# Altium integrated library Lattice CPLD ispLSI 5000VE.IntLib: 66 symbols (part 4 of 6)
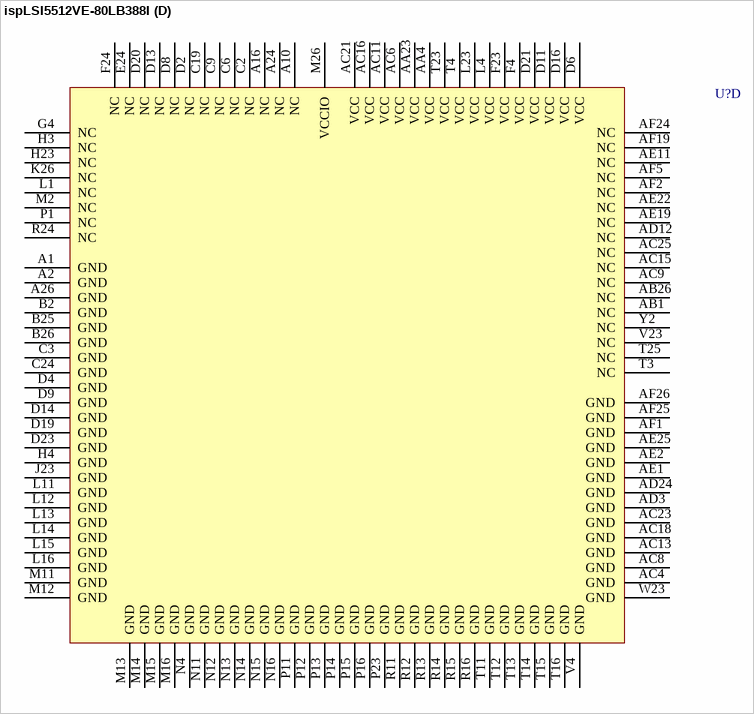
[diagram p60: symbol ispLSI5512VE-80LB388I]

## ispLSI5512VE-80LB388I
designator U?
ispLSI 5512VE SuperWIDE High Density PLD with 256 User I/Os, 12 ns, 3.3 V, Industrial Grade
footprint BGA388 (BGA, 388-Leads, Body 35x35mm, Pitch 1.27mm)
3D model 5512VE-BGA388 (388-Ball Ball Grid Array (BGA388))
part A pins: AA1 I/O18 (io), AA2 I/O16 (io), AA3 I/O22 (io), AA24 I/O114 (io), AA25 I/O112 (io), AA26 I/O115 (io), AB2 I/O20 (io), AB3 I/O26 (io), AB4 I/O24 (io), AB23 I/O109 (io), AB24 I/O110 (io), AB25 I/O108 (io), AC1 I/O25 (io), AC2 I/O23 (io), AC3 I/O28 (io), AC5 I/O37 (io), AC7 I/O41 (io), AC10 I/O56 (io), AC12 I/O64 (io), AC14 I/O68 (io), AC17 I/O79 (io), AC19 I/O86 (io), AC20 I/O90 (io), AC22 I/O97 (io), AC24 I/O106 (io), AC26 I/O107 (io), AD1 I/O29 (io), AD2 I/O27 (io), AD4 I/O34 (io), AD5 I/O38 (io), AD6 I/O42 (io), AD7 I/O46 (io), AD8 I/O50 (io), AD9 I/O54 (io), AD10 I/O58 (io), AD11 I/O62 (io), AD14 I/O70 (io), AD15 I/O73 (io), AD16 I/O77 (io), AD17 I/O81 (io), AD18 I/O84 (io), AD19 I/O88 (io), AD20 I/O92 (io), AD21 I/O95 (io), AD22 I/O99 (io), AD23 I/O101 (io), AD25 I/O104 (io), AD26 I/O105 (io), AE3 I/O31 (io), AE4 I/O33 (io), AE5 I/O36 (io), AE6 I/O40 (io), AE7 I/O44 (io), AE8 I/O47 (io), AE9 I/O51 (io), AE10 I/O53 (io), AE12 I/O60 (io), AE13 I/O63 (io), AE14 I/O67 (io), AE15 I/O69 (io), AE16 I/O72 (io), AE17 I/O76 (io), AE18 I/O80 (io), AE20 I/O85 (io), AE21 I/O89 (io), AE23 I/O96 (io), AE24 I/O100 (io), AE26 I/O103 (io), AF3 I/O32 (io), AF4 I/O35 (io), AF6 I/O43 (io), AF7 I/O45 (io), AF8 I/O49 (io), AF9 I/O52 (io), AF10 I/O55 (io), AF11 I/O59 (io), AF12 I/O61 (io), AF13 I/O65 (io), AF15 I/O71 (io), AF16 I/O74 (io), AF17 I/O78 (io), AF18 I/O82 (io), AF20 I/O87 (io), AF21 I/O91 (io), AF22 I/O94 (io), AF23 I/O98 (io), M25 I/O143 (io), N23 I/O140 (io), N25 I/O139 (io), N26 I/O141 (io), P24 I/O142 (io), P25 I/O135 (io), P26 I/O137 (io), R4 I/O1 (io), R23 I/O136 (io), R25 I/O132 (io), R26 I/O133 (io), T1 I/O0/TOE (io), T24 I/O134 (io), T26 I/O131 (io), U1 I/O4 (io), U2 I/O2 (io), U3 I/O7 (io), U4 I/O5 (io), U23 I/O128 (io), U24 I/O130 (io), U25 I/O125 (io), U26 I/O127 (io), V1 I/O8 (io), V2 I/O6 (io), V3 I/O11 (io), V24 I/O126 (io), V25 I/O123 (io), V26 I/O124 (io), W1 I/O10 (io), W2 I/O9 (io), W3 I/O15 (io), W4 I/O13 (io), W24 I/O122 (io), W25 I/O119 (io), W26 I/O121 (io), Y1 I/O14 (io), Y3 I/O19 (io), Y4 I/O17 (io), Y23 I/O113 (io), Y24 I/O118 (io), Y25 I/O116 (io), Y26 I/O117 (io)
part B pins: A3 I/O246 (io), A4 I/O242 (io), A5 I/O238 (io), A6 I/O235 (io), A7 I/O231 (io), A8 I/O228 (io), A9 I/O226 (io), A11 I/O218 (io), A12 I/O215 (io), A14 I/O209 (io), A15 I/O205 (io), A17 I/O199 (io), A18 I/O196 (io), A19 I/O193 (io), A20 I/O189 (io), A21 I/O187 (io), A22 I/O183 (io), A23 I/O179/CLK2 (io), A25 I/O174 (io), B1 I/O247 (io), B3 I/O244 (io), B4 I/O240 (io), B5 I/O237 (io), B6 I/O233 (io), B7 I/O229 (io), B8 I/O227 (io), B9 I/O224 (io), B10 I/O220 (io), B11 I/O216 (io), B12 I/O213 (io), B13 I/O211 (io), B14 I/O207 (io), B15 I/O204 (io), B16 I/O201 (io), B17 I/O197/CLK3 (io), B18 I/O195 (io), B19 I/O191 (io), B20 I/O188 (io), B21 I/O184 (io), B22 I/O180 (io), B23 I/O177 (io), B24 I/O175 (io), C1 I/O249 (io), C4 I/O245 (io), C5 I/O243 (io), C7 I/O236 (io), C8 I/O232 (io), C10 I/O225 (io), C11 I/O221 (io), C12 I/O217 (io), C13 I/O214 (io), C15 I/O210 (io), C16 I/O206 (io), C17 I/O202 (io), C18 I/O198 (io), C20 I/O190 (io), C21 I/O186 (io), C22 I/O182 (io), C23 I/O178 (io), C25 I/O171 (io), C26 I/O173 (io), D1 I/O251 (io), D3 I/O250 (io), D5 I/O241 (io), D7 I/O234 (io), D10 I/O223 (io), D12 I/O219 (io), D15 I/O208 (io), D17 I/O200 (io), D18 I/O192 (io), D22 I/O181 (io), D24 I/O172 (io), D25 I/O168 (io), D26 I/O170 (io), E1 I/O255 (io), E2 I/O252 (io), E3 I/O254 (io), E4 I/O253 (io), E23 I/O169 (io), E25 I/O165 (io), E26 I/O166 (io), F1 I/O259 (io), F2 I/O256 (io), F3 I/O258 (io), F25 I/O161 (io), F26 I/O163 (io), G1 I/O261 (io), G2 I/O260 (io), G3 I/O262 (io), G23 I/O162 (io), G24 I/O164 (io), G25 I/O157 (io), G26 I/O159 (io), H1 I/O265 (io), H2 I/O263 (io), H24 I/O160 (io), H25 I/O154 (io), H26 I/O155 (io), J1 I/O268 (io), J2 I/O267 (io), J3 I/O270 (io), J4 I/O264 (io), J24 I/O156 (io), J25 I/O151 (io), J26 I/O153 (io), K1 I/O271 (io), K2 I/O269 (io), K3 I/O274 (io), K4 I/O272 (io), K23 I/O150 (io), K24 I/O152 (io), K25 I/O147 (io), L2 I/O273 (io), L3 I/O277 (io), L24 I/O148 (io), L26 I/O145 (io), M1 I/O276 (io), M3 I/O281 (io), M4 I/O279 (io), M23 I/O146 (io), M24 I/O144 (io), N1 I/O280 (io), N2 I/O278 (io), N3 I/O285 (io), P2 I/O282 (io), P3 I/O287 (io), P4 I/O283 (io), R2 I/O286 (io)
part C pins: A13 CLK0 (in), AD13 GOE1 (in), AF14 GOE0 (in), C14 CLK1 (in), L25 RESET (in), N24 TDO (out), R1 TMS (in), R3 TDI (in), T2 TCK (in)
part D pins: A1 GND (power), A2 GND (power), A10 NC, A16 NC, A24 NC, A26 GND (power), AA4 VCC (power), AA23 VCC (power), AB1 NC, AB26 NC, AC4 GND (power), AC6 VCC (power), AC8 GND (power), AC9 NC, AC11 VCC (power), AC13 GND (power), AC15 NC, AC16 VCC (power), AC18 GND (power), AC21 VCC (power), AC23 GND (power), AC25 NC, AD3 GND (power), AD12 NC, AD24 GND (power), AE1 GND (power), AE2 GND (power), AE11 NC, AE19 NC, AE22 NC, AE25 GND (power), AF1 GND (power), AF2 NC, AF5 NC, AF19 NC, AF24 NC, AF25 GND (power), AF26 GND (power), B2 GND (power), B25 GND (power), B26 GND (power), C2 NC, C3 GND (power), C6 NC, C9 NC, C19 NC, C24 GND (power), D2 NC, D4 GND (power), D6 VCC (power), D8 NC, D9 GND (power), D11 VCC (power), D13 NC, D14 GND (power), D16 VCC (power), D19 GND (power), D20 NC, D21 VCC (power), D23 GND (power), E24 NC, F4 VCC (power), F23 VCC (power), F24 NC, G4 NC, H3 NC, H4 GND (power), H23 NC, J23 GND (power), K26 NC, L1 NC, L4 VCC (power), L11 GND (power), L12 GND (power), L13 GND (power), L14 GND (power), L15 GND (power), L16 GND (power), L23 VCC (power), M2 NC, M11 GND (power), M12 GND (power), M13 GND (power), M14 GND (power), M15 GND (power), M16 GND (power), M26 VCCIO (power), N4 GND (power), N11 GND (power), N12 GND (power), N13 GND (power), N14 GND (power), N15 GND (power), N16 GND (power), P1 NC, P11 GND (power), P12 GND (power), P13 GND (power), P14 GND (power), P15 GND (power), P16 GND (power), P23 GND (power), R11 GND (power), R12 GND (power), R13 GND (power), R14 GND (power), R15 GND (power), R16 GND (power), R24 NC, T3 NC, T4 VCC (power), T11 GND (power), T12 GND (power), T13 GND (power), T14 GND (power), T15 GND (power), T16 GND (power), T23 VCC (power), T25 NC, V4 GND (power), V23 NC, W23 GND (power), Y2 NC

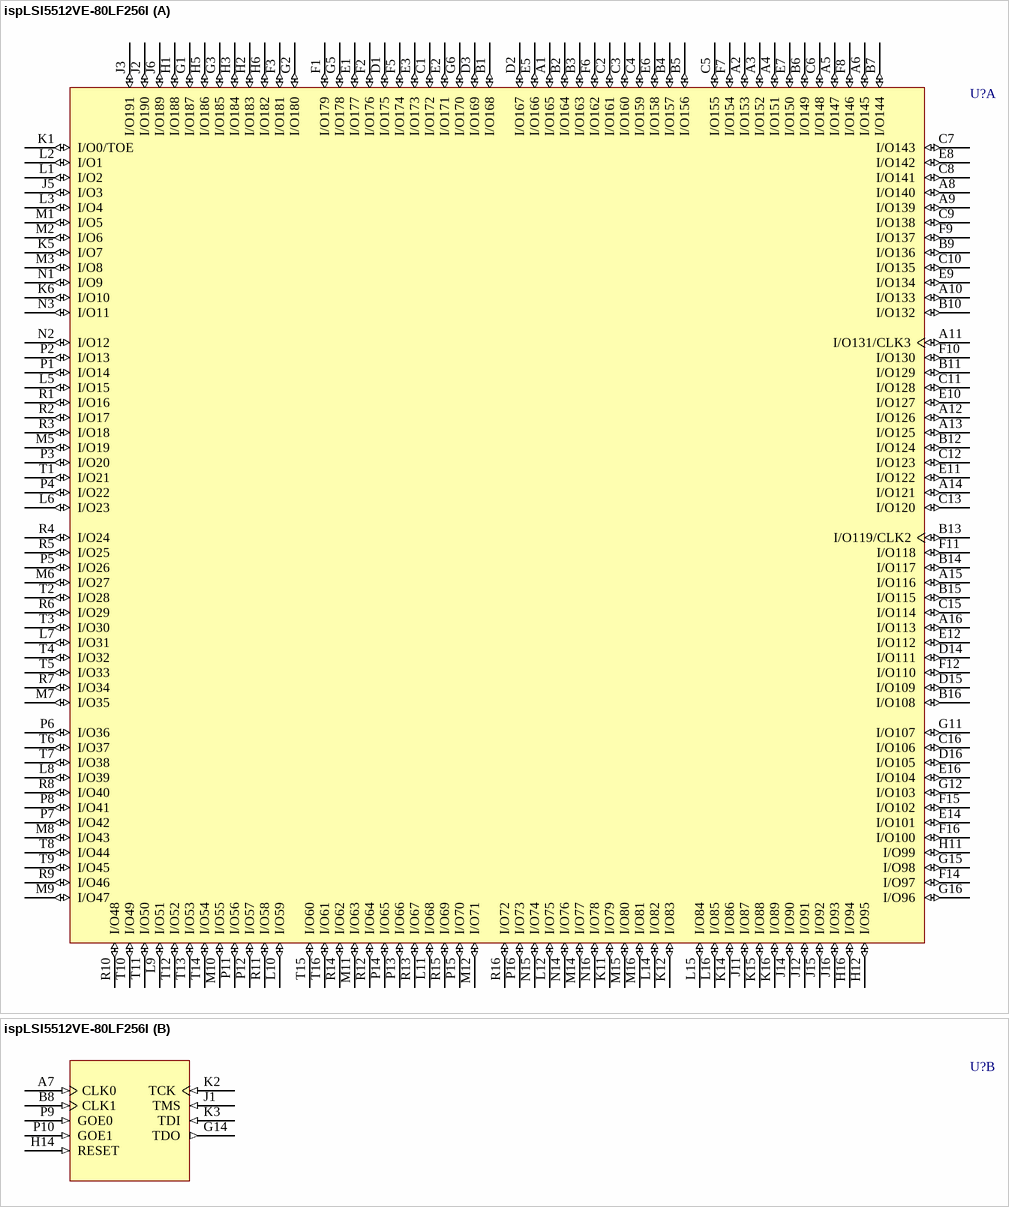
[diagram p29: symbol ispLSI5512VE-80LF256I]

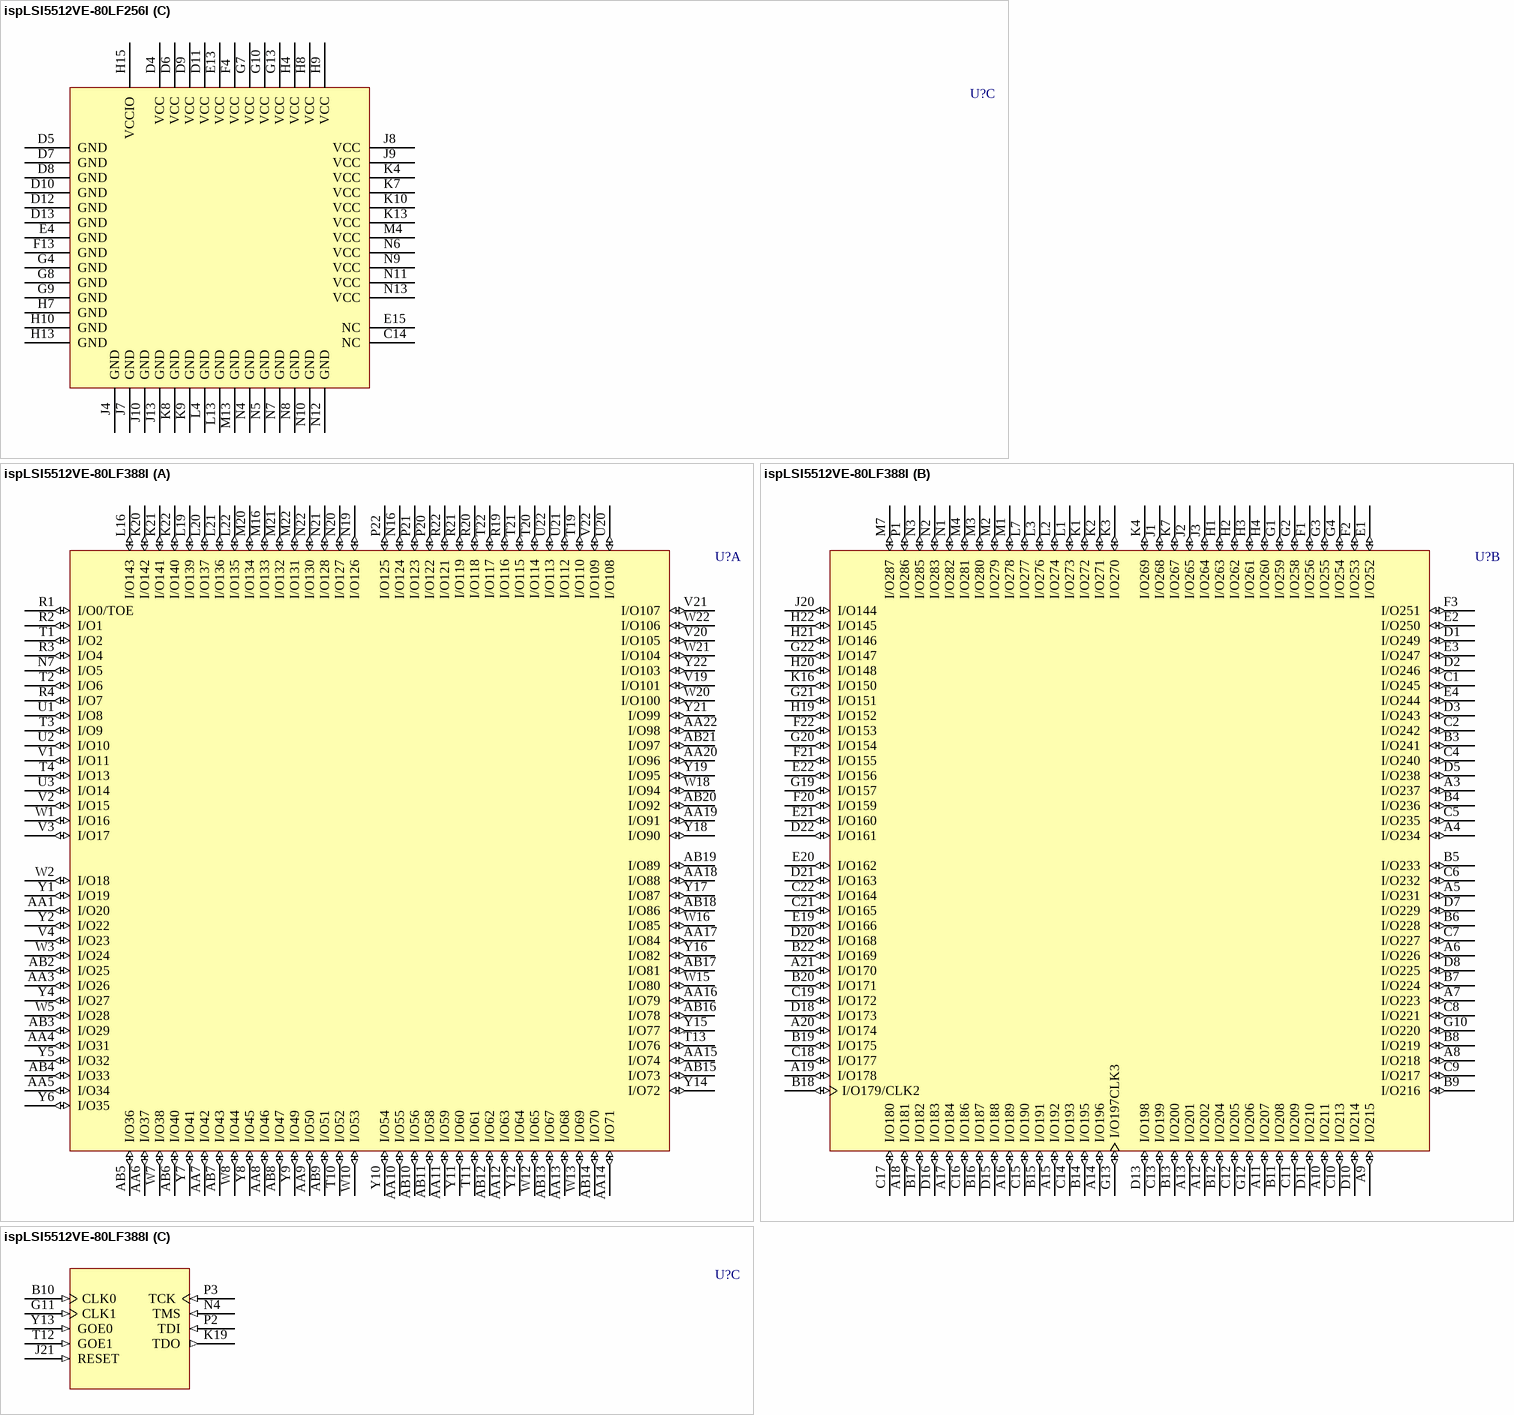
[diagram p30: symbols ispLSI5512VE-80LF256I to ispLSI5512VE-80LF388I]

## ispLSI5512VE-80LF256I
designator U?
ispLSI 5512VE SuperWIDE High Density PLD with 192 User I/Os, 12 ns, 3.3 V, Industrial Grade
footprint fpBGA256 (BGA, 256-Leads, Body 17x17mm, Pitch 1mm)
3D model 5512VE-fpBGA256 (256-Ball Fine Pitch Ball Grid Array (fpBGA256))
part A pins: A1 I/O165 (io), A2 I/O153 (io), A3 I/O152 (io), A4 I/O151 (io), A5 I/O147 (io), A6 I/O145 (io), A8 I/O140 (io), A9 I/O139 (io), A10 I/O133 (io), A11 I/O131/CLK3 (io), A12 I/O126 (io), A13 I/O125 (io), A14 I/O121 (io), A15 I/O116 (io), A16 I/O113 (io), B1 I/O168 (io), B2 I/O164 (io), B3 I/O163 (io), B4 I/O157 (io), B5 I/O156 (io), B6 I/O149 (io), B7 I/O144 (io), B9 I/O136 (io), B10 I/O132 (io), B11 I/O129 (io), B12 I/O124 (io), B13 I/O119/CLK2 (io), B14 I/O117 (io), B15 I/O115 (io), B16 I/O108 (io), C1 I/O172 (io), C2 I/O161 (io), C3 I/O160 (io), C4 I/O159 (io), C5 I/O155 (io), C6 I/O148 (io), C7 I/O143 (io), C8 I/O141 (io), C9 I/O138 (io), C10 I/O135 (io), C11 I/O128 (io), C12 I/O123 (io), C13 I/O120 (io), C15 I/O114 (io), C16 I/O106 (io), D1 I/O175 (io), D2 I/O167 (io), D3 I/O169 (io), D14 I/O111 (io), D15 I/O109 (io), D16 I/O105 (io), E1 I/O177 (io), E2 I/O171 (io), E3 I/O173 (io), E5 I/O166 (io), E6 I/O158 (io), E7 I/O150 (io), E8 I/O142 (io), E9 I/O134 (io), E10 I/O127 (io), E11 I/O122 (io), E12 I/O112 (io), E14 I/O101 (io), E16 I/O104 (io), F1 I/O179 (io), F2 I/O176 (io), F3 I/O181 (io), F5 I/O174 (io), F6 I/O162 (io), F7 I/O154 (io), F8 I/O146 (io), F9 I/O137 (io), F10 I/O130 (io), F11 I/O118 (io), F12 I/O110 (io), F14 I/O97 (io), F15 I/O102 (io), F16 I/O100 (io), G1 I/O187 (io), G2 I/O180 (io), G3 I/O185 (io), G5 I/O178 (io), G6 I/O170 (io), G11 I/O107 (io), G12 I/O103 (io), G15 I/O98 (io), G16 I/O96 (io), H1 I/O188 (io), H2 I/O183 (io), H3 I/O184 (io), H5 I/O186 (io), H6 I/O182 (io), H11 I/O99 (io), H12 I/O95 (io), H16 I/O94 (io), J2 I/O190 (io), J3 I/O191 (io), J5 I/O3 (io), J6 I/O189 (io), J11 I/O87 (io), J12 I/O91 (io), J14 I/O90 (io), J15 I/O92 (io), J16 I/O93 (io), K1 I/O0/TOE (io), K5 I/O7 (io), K6 I/O10 (io), K11 I/O79 (io), K12 I/O83 (io), K14 I/O86 (io), K15 I/O88 (io), K16 I/O89 (io), L1 I/O2 (io), L2 I/O1 (io), L3 I/O4 (io), L5 I/O15 (io), L6 I/O23 (io), L7 I/O31 (io), L8 I/O39 (io), L9 I/O51 (io), L10 I/O59 (io), L11 I/O68 (io), L12 I/O75 (io), L14 I/O82 (io), L15 I/O84 (io), L16 I/O85 (io), M1 I/O5 (io), M2 I/O6 (io), M3 I/O8 (io), M5 I/O19 (io), M6 I/O27 (io), M7 I/O35 (io), M8 I/O43 (io), M9 I/O47 (io), M10 I/O55 (io), M11 I/O63 (io), M12 I/O71 (io), M14 I/O77 (io), M15 I/O80 (io), M16 I/O81 (io), N1 I/O9 (io), N2 I/O12 (io), N3 I/O11 (io), N14 I/O76 (io), N15 I/O74 (io), N16 I/O78 (io), P1 I/O14 (io), P2 I/O13 (io), P3 I/O20 (io), P4 I/O22 (io), P5 I/O26 (io), P6 I/O36 (io), P7 I/O42 (io), P8 I/O41 (io), P11 I/O56 (io), P12 I/O57 (io), P13 I/O66 (io), P14 I/O65 (io), P15 I/O70 (io), P16 I/O73 (io), R1 I/O16 (io), R2 I/O17 (io), R3 I/O18 (io), R4 I/O24 (io), R5 I/O25 (io), R6 I/O29 (io), R7 I/O34 (io), R8 I/O40 (io), R9 I/O46 (io), R10 I/O48 (io), R11 I/O58 (io), R12 I/O64 (io), R13 I/O67 (io), R14 I/O62 (io), R15 I/O69 (io), R16 I/O72 (io), T1 I/O21 (io), T2 I/O28 (io), T3 I/O30 (io), T4 I/O32 (io), T5 I/O33 (io), T6 I/O37 (io), T7 I/O38 (io), T8 I/O44 (io), T9 I/O45 (io), T10 I/O49 (io), T11 I/O50 (io), T12 I/O52 (io), T13 I/O53 (io), T14 I/O54 (io), T15 I/O60 (io), T16 I/O61 (io)
part B pins: A7 CLK0 (in), B8 CLK1 (in), G14 TDO (out), H14 RESET (in), J1 TMS (in), K2 TCK (in), K3 TDI (in), P9 GOE0 (in), P10 GOE1 (in)
part C pins: C14 NC, D4 VCC (power), D5 GND (power), D6 VCC (power), D7 GND (power), D8 GND (power), D9 VCC (power), D10 GND (power), D11 VCC (power), D12 GND (power), D13 GND (power), E4 GND (power), E13 VCC (power), E15 NC, F4 VCC (power), F13 GND (power), G4 GND (power), G7 VCC (power), G8 GND (power), G9 GND (power), G10 VCC (power), G13 VCC (power), H4 VCC (power), H7 GND (power), H8 VCC (power), H9 VCC (power), H10 GND (power), H13 GND (power), H15 VCCIO (power), J4 GND (power), J7 GND (power), J8 VCC (power), J9 VCC (power), J10 GND (power), J13 GND (power), K4 VCC (power), K7 VCC (power), K8 GND (power), K9 GND (power), K10 VCC (power), K13 VCC (power), L4 GND (power), L13 GND (power), M4 VCC (power), M13 GND (power), N4 GND (power), N5 GND (power), N6 VCC (power), N7 GND (power), N8 GND (power), N9 VCC (power), N10 GND (power), N11 VCC (power), N12 GND (power), N13 VCC (power)

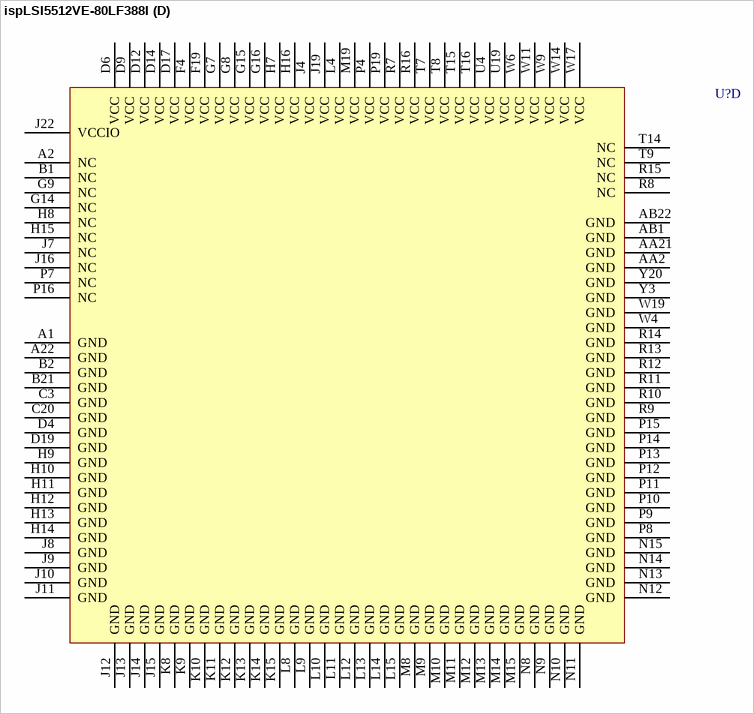
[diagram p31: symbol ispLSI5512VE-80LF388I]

## ispLSI5512VE-80LF388I
designator U?
ispLSI 5512VE SuperWIDE High Density PLD with 256 User I/Os, 12 ns, 3.3 V, Industrial Grade
footprint fpBGA388 (BGA, 388-Leads, Body 23x23mm, Pitch 1mm)
3D model 5512VE-fpBGA388 (388-Ball Fine Pitch Ball Grid Array (fpBGA388))
part A pins: AA1 I/O20 (io), AA3 I/O26 (io), AA4 I/O31 (io), AA5 I/O34 (io), AA6 I/O37 (io), AA7 I/O42 (io), AA8 I/O46 (io), AA9 I/O50 (io), AA10 I/O55 (io), AA11 I/O59 (io), AA12 I/O63 (io), AA13 I/O68 (io), AA14 I/O71 (io), AA15 I/O74 (io), AA16 I/O79 (io), AA17 I/O84 (io), AA18 I/O88 (io), AA19 I/O91 (io), AA20 I/O96 (io), AA22 I/O98 (io), AB2 I/O25 (io), AB3 I/O29 (io), AB4 I/O33 (io), AB5 I/O36 (io), AB6 I/O40 (io), AB7 I/O43 (io), AB8 I/O47 (io), AB9 I/O51 (io), AB10 I/O56 (io), AB11 I/O58 (io), AB12 I/O62 (io), AB13 I/O67 (io), AB14 I/O70 (io), AB15 I/O73 (io), AB16 I/O78 (io), AB17 I/O81 (io), AB18 I/O86 (io), AB19 I/O89 (io), AB20 I/O92 (io), AB21 I/O97 (io), K20 I/O142 (io), K21 I/O141 (io), K22 I/O140 (io), L16 I/O143 (io), L19 I/O139 (io), L20 I/O137 (io), L21 I/O136 (io), L22 I/O135 (io), M16 I/O133 (io), M20 I/O134 (io), M21 I/O132 (io), M22 I/O131 (io), N7 I/O5 (io), N16 I/O124 (io), N19 I/O126 (io), N20 I/O127 (io), N21 I/O128 (io), N22 I/O130 (io), P20 I/O122 (io), P21 I/O123 (io), P22 I/O125 (io), R1 I/O0/TOE (io), R2 I/O1 (io), R3 I/O4 (io), R4 I/O7 (io), R19 I/O116 (io), R20 I/O118 (io), R21 I/O119 (io), R22 I/O121 (io), T1 I/O2 (io), T2 I/O6 (io), T3 I/O9 (io), T4 I/O13 (io), T10 I/O52 (io), T11 I/O61 (io), T13 I/O76 (io), T19 I/O110 (io), T20 I/O114 (io), T21 I/O115 (io), T22 I/O117 (io), U1 I/O8 (io), U2 I/O10 (io), U3 I/O14 (io), U20 I/O108 (io), U21 I/O112 (io), U22 I/O113 (io), V1 I/O11 (io), V2 I/O15 (io), V3 I/O17 (io), V4 I/O23 (io), V19 I/O101 (io), V20 I/O105 (io), V21 I/O107 (io), V22 I/O109 (io), W1 I/O16 (io), W2 I/O18 (io), W3 I/O24 (io), W5 I/O28 (io), W7 I/O38 (io), W8 I/O44 (io), W10 I/O53 (io), W12 I/O65 (io), W13 I/O69 (io), W15 I/O80 (io), W16 I/O85 (io), W18 I/O94 (io), W20 I/O100 (io), W21 I/O104 (io), W22 I/O106 (io), Y1 I/O19 (io), Y2 I/O22 (io), Y4 I/O27 (io), Y5 I/O32 (io), Y6 I/O35 (io), Y7 I/O41 (io), Y8 I/O45 (io), Y9 I/O49 (io), Y10 I/O54 (io), Y11 I/O60 (io), Y12 I/O64 (io), Y14 I/O72 (io), Y15 I/O77 (io), Y16 I/O82 (io), Y17 I/O87 (io), Y18 I/O90 (io), Y19 I/O95 (io), Y21 I/O99 (io), Y22 I/O103 (io)
part B pins: A3 I/O237 (io), A4 I/O234 (io), A5 I/O231 (io), A6 I/O226 (io), A7 I/O223 (io), A8 I/O218 (io), A9 I/O215 (io), A10 I/O211 (io), A11 I/O207 (io), A12 I/O202 (io), A13 I/O201 (io), A14 I/O196 (io), A15 I/O192 (io), A16 I/O189 (io), A17 I/O184 (io), A18 I/O181 (io), A19 I/O178 (io), A20 I/O174 (io), A21 I/O170 (io), B3 I/O241 (io), B4 I/O236 (io), B5 I/O233 (io), B6 I/O228 (io), B7 I/O224 (io), B8 I/O219 (io), B9 I/O216 (io), B11 I/O208 (io), B12 I/O204 (io), B13 I/O200 (io), B14 I/O195 (io), B15 I/O191 (io), B16 I/O187 (io), B17 I/O182 (io), B18 I/O179/CLK2 (io), B19 I/O175 (io), B20 I/O171 (io), B22 I/O169 (io), C1 I/O245 (io), C2 I/O242 (io), C4 I/O240 (io), C5 I/O235 (io), C6 I/O232 (io), C7 I/O227 (io), C8 I/O221 (io), C9 I/O217 (io), C10 I/O213 (io), C11 I/O209 (io), C12 I/O205 (io), C13 I/O199 (io), C14 I/O193 (io), C15 I/O190 (io), C16 I/O186 (io), C17 I/O180 (io), C18 I/O177 (io), C19 I/O172 (io), C21 I/O165 (io), C22 I/O164 (io), D1 I/O249 (io), D2 I/O246 (io), D3 I/O243 (io), D5 I/O238 (io), D7 I/O229 (io), D8 I/O225 (io), D10 I/O214 (io), D11 I/O210 (io), D13 I/O198 (io), D15 I/O188 (io), D16 I/O183 (io), D18 I/O173 (io), D20 I/O168 (io), D21 I/O163 (io), D22 I/O161 (io), E1 I/O252 (io), E2 I/O250 (io), E3 I/O247 (io), E4 I/O244 (io), E19 I/O166 (io), E20 I/O162 (io), E21 I/O160 (io), E22 I/O156 (io), F1 I/O256 (io), F2 I/O253 (io), F3 I/O251 (io), F20 I/O159 (io), F21 I/O155 (io), F22 I/O153 (io), G1 I/O259 (io), G2 I/O258 (io), G3 I/O255 (io), G4 I/O254 (io), G10 I/O220 (io), G12 I/O206 (io), G13 I/O197CLK3 (io), G19 I/O157 (io), G20 I/O154 (io), G21 I/O151 (io), G22 I/O147 (io), H1 I/O263 (io), H2 I/O262 (io), H3 I/O261 (io), H4 I/O260 (io), H19 I/O152 (io), H20 I/O148 (io), H21 I/O146 (io), H22 I/O145 (io), J1 I/O268 (io), J2 I/O265 (io), J3 I/O264 (io), J20 I/O144 (io), K1 I/O272 (io), K2 I/O271 (io), K3 I/O270 (io), K4 I/O269 (io), K7 I/O267 (io), K16 I/O150 (io), L1 I/O273 (io), L2 I/O274 (io), L3 I/O276 (io), L7 I/O277 (io), M1 I/O278 (io), M2 I/O279 (io), M3 I/O280 (io), M4 I/O281 (io), M7 I/O287 (io), N1 I/O282 (io), N2 I/O283 (io), N3 I/O285 (io), P1 I/O286 (io)
part C pins: B10 CLK0 (in), G11 CLK1 (in), J21 RESET (in), K19 TDO (out), N4 TMS (in), P2 TDI (in), P3 TCK (in), T12 GOE1 (in), Y13 GOE0 (in)
part D pins: A1 GND (power), A2 NC, A22 GND (power), AA2 GND (power), AA21 GND (power), AB1 GND (power), AB22 GND (power), B1 NC, B2 GND (power), B21 GND (power), C3 GND (power), C20 GND (power), D4 GND (power), D6 VCC (power), D9 VCC (power), D12 VCC (power), D14 VCC (power), D17 VCC (power), D19 GND (power), F4 VCC (power), F19 VCC (power), G7 VCC (power), G8 VCC (power), G9 NC, G14 NC, G15 VCC (power), G16 VCC (power), H7 VCC (power), H8 NC, H9 GND (power), H10 GND (power), H11 GND (power), H12 GND (power), H13 GND (power), H14 GND (power), H15 NC, H16 VCC (power), J4 VCC (power), J7 NC, J8 GND (power), J9 GND (power), J10 GND (power), J11 GND (power), J12 GND (power), J13 GND (power), J14 GND (power), J15 GND (power), J16 NC, J19 VCC (power), J22 VCCIO (power), K8 GND (power), K9 GND (power), K10 GND (power), K11 GND (power), K12 GND (power), K13 GND (power), K14 GND (power), K15 GND (power), L4 VCC (power), L8 GND (power), L9 GND (power), L10 GND (power), L11 GND (power), L12 GND (power), L13 GND (power), L14 GND (power), L15 GND (power), M8 GND (power), M9 GND (power), M10 GND (power), M11 GND (power), M12 GND (power), M13 GND (power), M14 GND (power), M15 GND (power), M19 VCC (power), N8 GND (power), N9 GND (power), N10 GND (power), N11 GND (power), N12 GND (power), N13 GND (power), N14 GND (power), N15 GND (power), P4 VCC (power), P7 NC, P8 GND (power), P9 GND (power), P10 GND (power), P11 GND (power), P12 GND (power), P13 GND (power), P14 GND (power), P15 GND (power), P16 NC, P19 VCC (power), R7 VCC (power), R8 NC, R9 GND (power), R10 GND (power), R11 GND (power), R12 GND (power), R13 GND (power), R14 GND (power), R15 NC, R16 VCC (power), T7 VCC (power), T8 VCC (power), T9 NC, T14 NC, T15 VCC (power), T16 VCC (power), U4 VCC (power), U19 VCC (power), W4 GND (power), W6 VCC (power), W9 VCC (power), W11 VCC (power), W14 VCC (power), W17 VCC (power), W19 GND (power), Y3 GND (power), Y20 GND (power)

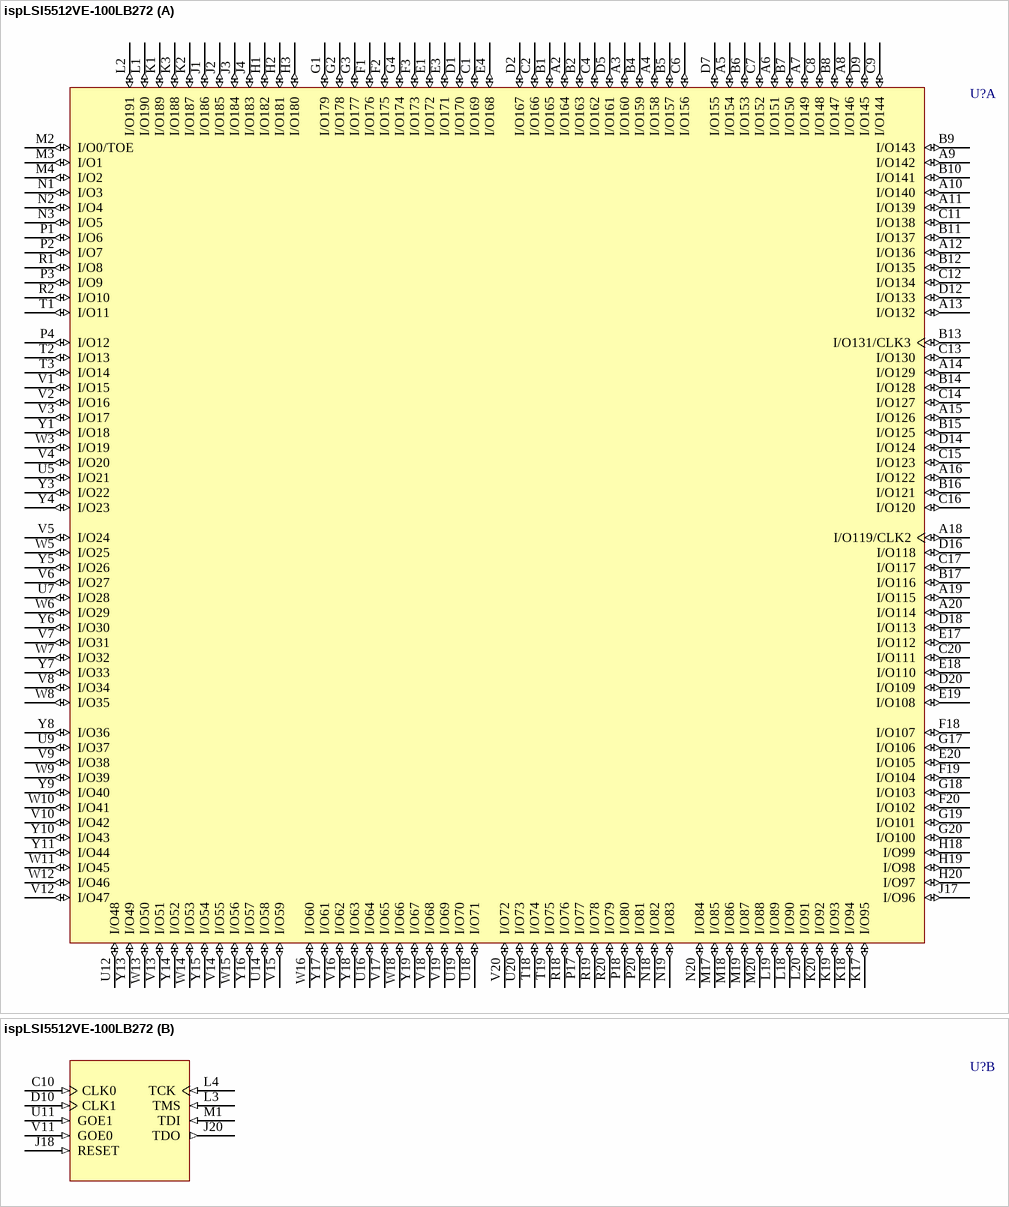
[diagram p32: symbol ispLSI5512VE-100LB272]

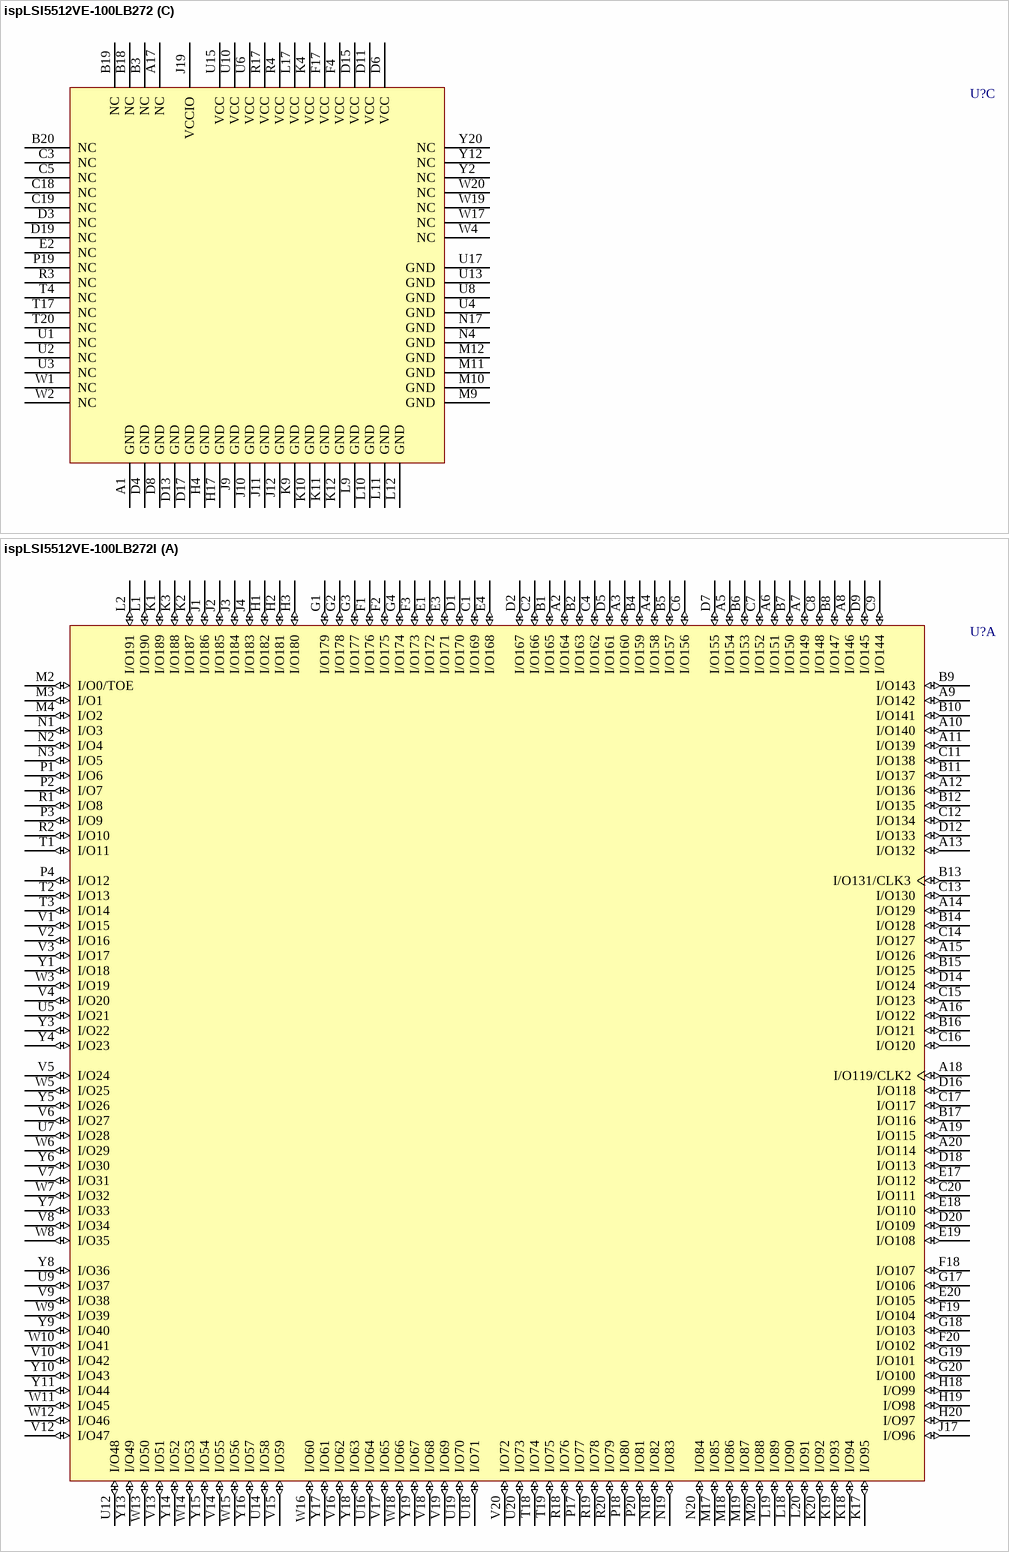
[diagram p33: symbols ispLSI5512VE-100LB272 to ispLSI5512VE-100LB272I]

## ispLSI5512VE-100LB272
designator U?
ispLSI 5512VE SuperWIDE High Density PLD with 192 User I/Os, 10 ns, 3.3 V, Commercial Grade
footprint BGA272 (BGA, 272-Leads, Body 27x27mm, Pitch 1.27mm)
3D model 5512VE-BGA272 (272-Ball Ball Grid Array (BGA272))
part A pins: A2 I/O164 (io), A3 I/O160 (io), A4 I/O158 (io), A5 I/O154 (io), A6 I/O151 (io), A7 I/O149 (io), A8 I/O146 (io), A9 I/O142 (io), A10 I/O140 (io), A11 I/O139 (io), A12 I/O136 (io), A13 I/O132 (io), A14 I/O129 (io), A15 I/O126 (io), A16 I/O122 (io), A18 I/O119/CLK2 (io), A19 I/O115 (io), A20 I/O114 (io), B1 I/O165 (io), B2 I/O163 (io), B4 I/O159 (io), B5 I/O157 (io), B6 I/O153 (io), B7 I/O150 (io), B8 I/O147 (io), B9 I/O143 (io), B10 I/O141 (io), B11 I/O137 (io), B12 I/O135 (io), B13 I/O131/CLK3 (io), B14 I/O128 (io), B15 I/O125 (io), B16 I/O121 (io), B17 I/O116 (io), C1 I/O169 (io), C2 I/O166 (io), C4 I/O162 (io), C6 I/O156 (io), C7 I/O152 (io), C8 I/O148 (io), C9 I/O144 (io), C11 I/O138 (io), C12 I/O134 (io), C13 I/O130 (io), C14 I/O127 (io), C15 I/O123 (io), C16 I/O120 (io), C17 I/O117 (io), C20 I/O111 (io), D1 I/O170 (io), D2 I/O167 (io), D5 I/O161 (io), D7 I/O155 (io), D9 I/O145 (io), D12 I/O133 (io), D14 I/O124 (io), D16 I/O118 (io), D18 I/O113 (io), D20 I/O109 (io), E1 I/O172 (io), E3 I/O171 (io), E4 I/O168 (io), E17 I/O112 (io), E18 I/O110 (io), E19 I/O108 (io), E20 I/O105 (io), F1 I/O176 (io), F2 I/O175 (io), F3 I/O173 (io), F18 I/O107 (io), F19 I/O104 (io), F20 I/O102 (io), G1 I/O179 (io), G2 I/O178 (io), G3 I/O177 (io), G4 I/O174 (io), G17 I/O106 (io), G18 I/O103 (io), G19 I/O101 (io), G20 I/O100 (io), H1 I/O182 (io), H2 I/O181 (io), H3 I/O180 (io), H18 I/O99 (io), H19 I/O98 (io), H20 I/O97 (io), J1 I/O186 (io), J2 I/O185 (io), J3 I/O184 (io), J4 I/O183 (io), J17 I/O96 (io), K1 I/O189 (io), K2 I/O187 (io), K3 I/O188 (io), K17 I/O95 (io), K18 I/O94 (io), K19 I/O93 (io), K20 I/O92 (io), L1 I/O190 (io), L2 I/O191 (io), L18 I/O90 (io), L19 I/O89 (io), L20 I/O91 (io), M2 I/O0/TOE (io), M3 I/O1 (io), M4 I/O2 (io), M17 I/O85 (io), M18 I/O86 (io), M19 I/O87 (io), M20 I/O88 (io), N1 I/O3 (io), N2 I/O4 (io), N3 I/O5 (io), N18 I/O82 (io), N19 I/O83 (io), N20 I/O84 (io), P1 I/O6 (io), P2 I/O7 (io), P3 I/O9 (io), P4 I/O12 (io), P17 I/O77 (io), P18 I/O80 (io), P20 I/O81 (io), R1 I/O8 (io), R2 I/O10 (io), R18 I/O76 (io), R19 I/O78 (io), R20 I/O79 (io), T1 I/O11 (io), T2 I/O13 (io), T3 I/O14 (io), T18 I/O74 (io), T19 I/O75 (io), U5 I/O21 (io), U7 I/O28 (io), U9 I/O37 (io), U12 I/O48 (io), U14 I/O58 (io), U16 I/O64 (io), U18 I/O71 (io), U19 I/O70 (io), U20 I/O73 (io), V1 I/O15 (io), V2 I/O16 (io), V3 I/O17 (io), V4 I/O20 (io), V5 I/O24 (io), V6 I/O27 (io), V7 I/O31 (io), V8 I/O34 (io), V9 I/O38 (io), V10 I/O42 (io), V12 I/O47 (io), V13 I/O51 (io), V14 I/O55 (io), V15 I/O59 (io), V16 I/O62 (io), V17 I/O65 (io), V18 I/O68 (io), V19 I/O69 (io), V20 I/O72 (io), W3 I/O19 (io), W5 I/O25 (io), W6 I/O29 (io), W7 I/O32 (io), W8 I/O35 (io), W9 I/O39 (io), W10 I/O41 (io), W11 I/O45 (io), W12 I/O46 (io), W13 I/O50 (io), W14 I/O53 (io), W15 I/O56 (io), W16 I/O60 (io), W18 I/O66 (io), Y1 I/O18 (io), Y3 I/O22 (io), Y4 I/O23 (io), Y5 I/O26 (io), Y6 I/O30 (io), Y7 I/O33 (io), Y8 I/O36 (io), Y9 I/O40 (io), Y10 I/O43 (io), Y11 I/O44 (io), Y13 I/O49 (io), Y14 I/O52 (io), Y15 I/O54 (io), Y16 I/O57 (io), Y17 I/O61 (io), Y18 I/O63 (io), Y19 I/O67 (io)
part B pins: C10 CLK0 (in), D10 CLK1 (in), J18 RESET (in), J20 TDO (out), L3 TMS (in), L4 TCK (in), M1 TDI (in), U11 GOE1 (in), V11 GOE0 (in)
part C pins: A1 GND (power), A17 NC, B3 NC, B18 NC, B19 NC, B20 NC, C3 NC, C5 NC, C18 NC, C19 NC, D3 NC, D4 GND (power), D6 VCC (power), D8 GND (power), D11 VCC (power), D13 GND (power), D15 VCC (power), D17 GND (power), D19 NC, E2 NC, F4 VCC (power), F17 VCC (power), H4 GND (power), H17 GND (power), J9 GND (power), J10 GND (power), J11 GND (power), J12 GND (power), J19 VCCIO (power), K4 VCC (power), K9 GND (power), K10 GND (power), K11 GND (power), K12 GND (power), L9 GND (power), L10 GND (power), L11 GND (power), L12 GND (power), L17 VCC (power), M9 GND (power), M10 GND (power), M11 GND (power), M12 GND (power), N4 GND (power), N17 GND (power), P19 NC, R3 NC, R4 VCC (power), R17 VCC (power), T4 NC, T17 NC, T20 NC, U1 NC, U2 NC, U3 NC, U4 GND (power), U6 VCC (power), U8 GND (power), U10 VCC (power), U13 GND (power), U15 VCC (power), U17 GND (power), W1 NC, W2 NC, W4 NC, W17 NC, W19 NC, W20 NC, Y2 NC, Y12 NC, Y20 NC

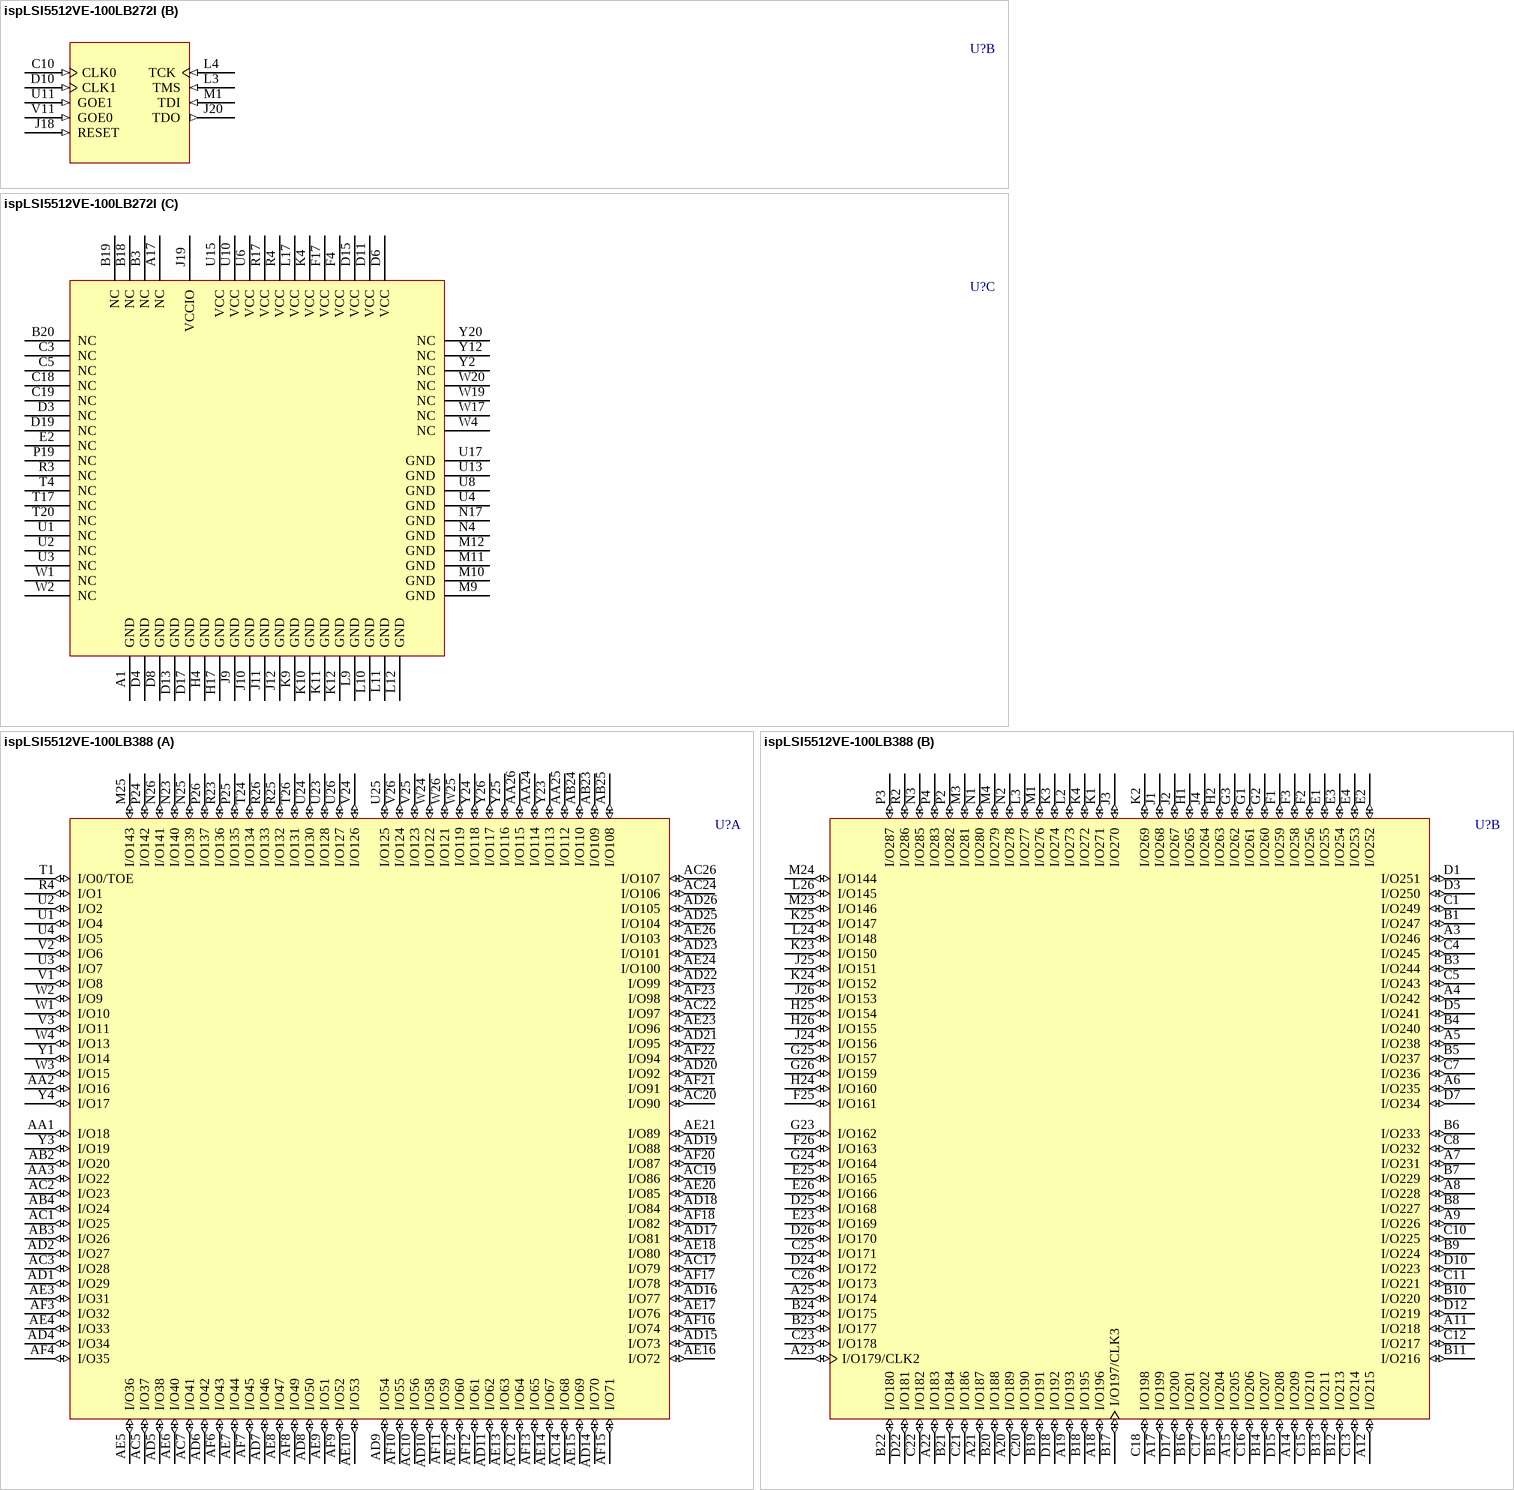
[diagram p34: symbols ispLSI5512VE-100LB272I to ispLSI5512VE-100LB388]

## ispLSI5512VE-100LB272I
designator U?
ispLSI 5512VE SuperWIDE High Density PLD with 192 User I/Os, 10 ns, 3.3 V, Industrial Grade
footprint BGA272 (BGA, 272-Leads, Body 27x27mm, Pitch 1.27mm)
3D model 5512VE-BGA272 (272-Ball Ball Grid Array (BGA272))
part A pins: A2 I/O164 (io), A3 I/O160 (io), A4 I/O158 (io), A5 I/O154 (io), A6 I/O151 (io), A7 I/O149 (io), A8 I/O146 (io), A9 I/O142 (io), A10 I/O140 (io), A11 I/O139 (io), A12 I/O136 (io), A13 I/O132 (io), A14 I/O129 (io), A15 I/O126 (io), A16 I/O122 (io), A18 I/O119/CLK2 (io), A19 I/O115 (io), A20 I/O114 (io), B1 I/O165 (io), B2 I/O163 (io), B4 I/O159 (io), B5 I/O157 (io), B6 I/O153 (io), B7 I/O150 (io), B8 I/O147 (io), B9 I/O143 (io), B10 I/O141 (io), B11 I/O137 (io), B12 I/O135 (io), B13 I/O131/CLK3 (io), B14 I/O128 (io), B15 I/O125 (io), B16 I/O121 (io), B17 I/O116 (io), C1 I/O169 (io), C2 I/O166 (io), C4 I/O162 (io), C6 I/O156 (io), C7 I/O152 (io), C8 I/O148 (io), C9 I/O144 (io), C11 I/O138 (io), C12 I/O134 (io), C13 I/O130 (io), C14 I/O127 (io), C15 I/O123 (io), C16 I/O120 (io), C17 I/O117 (io), C20 I/O111 (io), D1 I/O170 (io), D2 I/O167 (io), D5 I/O161 (io), D7 I/O155 (io), D9 I/O145 (io), D12 I/O133 (io), D14 I/O124 (io), D16 I/O118 (io), D18 I/O113 (io), D20 I/O109 (io), E1 I/O172 (io), E3 I/O171 (io), E4 I/O168 (io), E17 I/O112 (io), E18 I/O110 (io), E19 I/O108 (io), E20 I/O105 (io), F1 I/O176 (io), F2 I/O175 (io), F3 I/O173 (io), F18 I/O107 (io), F19 I/O104 (io), F20 I/O102 (io), G1 I/O179 (io), G2 I/O178 (io), G3 I/O177 (io), G4 I/O174 (io), G17 I/O106 (io), G18 I/O103 (io), G19 I/O101 (io), G20 I/O100 (io), H1 I/O182 (io), H2 I/O181 (io), H3 I/O180 (io), H18 I/O99 (io), H19 I/O98 (io), H20 I/O97 (io), J1 I/O186 (io), J2 I/O185 (io), J3 I/O184 (io), J4 I/O183 (io), J17 I/O96 (io), K1 I/O189 (io), K2 I/O187 (io), K3 I/O188 (io), K17 I/O95 (io), K18 I/O94 (io), K19 I/O93 (io), K20 I/O92 (io), L1 I/O190 (io), L2 I/O191 (io), L18 I/O90 (io), L19 I/O89 (io), L20 I/O91 (io), M2 I/O0/TOE (io), M3 I/O1 (io), M4 I/O2 (io), M17 I/O85 (io), M18 I/O86 (io), M19 I/O87 (io), M20 I/O88 (io), N1 I/O3 (io), N2 I/O4 (io), N3 I/O5 (io), N18 I/O82 (io), N19 I/O83 (io), N20 I/O84 (io), P1 I/O6 (io), P2 I/O7 (io), P3 I/O9 (io), P4 I/O12 (io), P17 I/O77 (io), P18 I/O80 (io), P20 I/O81 (io), R1 I/O8 (io), R2 I/O10 (io), R18 I/O76 (io), R19 I/O78 (io), R20 I/O79 (io), T1 I/O11 (io), T2 I/O13 (io), T3 I/O14 (io), T18 I/O74 (io), T19 I/O75 (io), U5 I/O21 (io), U7 I/O28 (io), U9 I/O37 (io), U12 I/O48 (io), U14 I/O58 (io), U16 I/O64 (io), U18 I/O71 (io), U19 I/O70 (io), U20 I/O73 (io), V1 I/O15 (io), V2 I/O16 (io), V3 I/O17 (io), V4 I/O20 (io), V5 I/O24 (io), V6 I/O27 (io), V7 I/O31 (io), V8 I/O34 (io), V9 I/O38 (io), V10 I/O42 (io), V12 I/O47 (io), V13 I/O51 (io), V14 I/O55 (io), V15 I/O59 (io), V16 I/O62 (io), V17 I/O65 (io), V18 I/O68 (io), V19 I/O69 (io), V20 I/O72 (io), W3 I/O19 (io), W5 I/O25 (io), W6 I/O29 (io), W7 I/O32 (io), W8 I/O35 (io), W9 I/O39 (io), W10 I/O41 (io), W11 I/O45 (io), W12 I/O46 (io), W13 I/O50 (io), W14 I/O53 (io), W15 I/O56 (io), W16 I/O60 (io), W18 I/O66 (io), Y1 I/O18 (io), Y3 I/O22 (io), Y4 I/O23 (io), Y5 I/O26 (io), Y6 I/O30 (io), Y7 I/O33 (io), Y8 I/O36 (io), Y9 I/O40 (io), Y10 I/O43 (io), Y11 I/O44 (io), Y13 I/O49 (io), Y14 I/O52 (io), Y15 I/O54 (io), Y16 I/O57 (io), Y17 I/O61 (io), Y18 I/O63 (io), Y19 I/O67 (io)
part B pins: C10 CLK0 (in), D10 CLK1 (in), J18 RESET (in), J20 TDO (out), L3 TMS (in), L4 TCK (in), M1 TDI (in), U11 GOE1 (in), V11 GOE0 (in)
part C pins: A1 GND (power), A17 NC, B3 NC, B18 NC, B19 NC, B20 NC, C3 NC, C5 NC, C18 NC, C19 NC, D3 NC, D4 GND (power), D6 VCC (power), D8 GND (power), D11 VCC (power), D13 GND (power), D15 VCC (power), D17 GND (power), D19 NC, E2 NC, F4 VCC (power), F17 VCC (power), H4 GND (power), H17 GND (power), J9 GND (power), J10 GND (power), J11 GND (power), J12 GND (power), J19 VCCIO (power), K4 VCC (power), K9 GND (power), K10 GND (power), K11 GND (power), K12 GND (power), L9 GND (power), L10 GND (power), L11 GND (power), L12 GND (power), L17 VCC (power), M9 GND (power), M10 GND (power), M11 GND (power), M12 GND (power), N4 GND (power), N17 GND (power), P19 NC, R3 NC, R4 VCC (power), R17 VCC (power), T4 NC, T17 NC, T20 NC, U1 NC, U2 NC, U3 NC, U4 GND (power), U6 VCC (power), U8 GND (power), U10 VCC (power), U13 GND (power), U15 VCC (power), U17 GND (power), W1 NC, W2 NC, W4 NC, W17 NC, W19 NC, W20 NC, Y2 NC, Y12 NC, Y20 NC

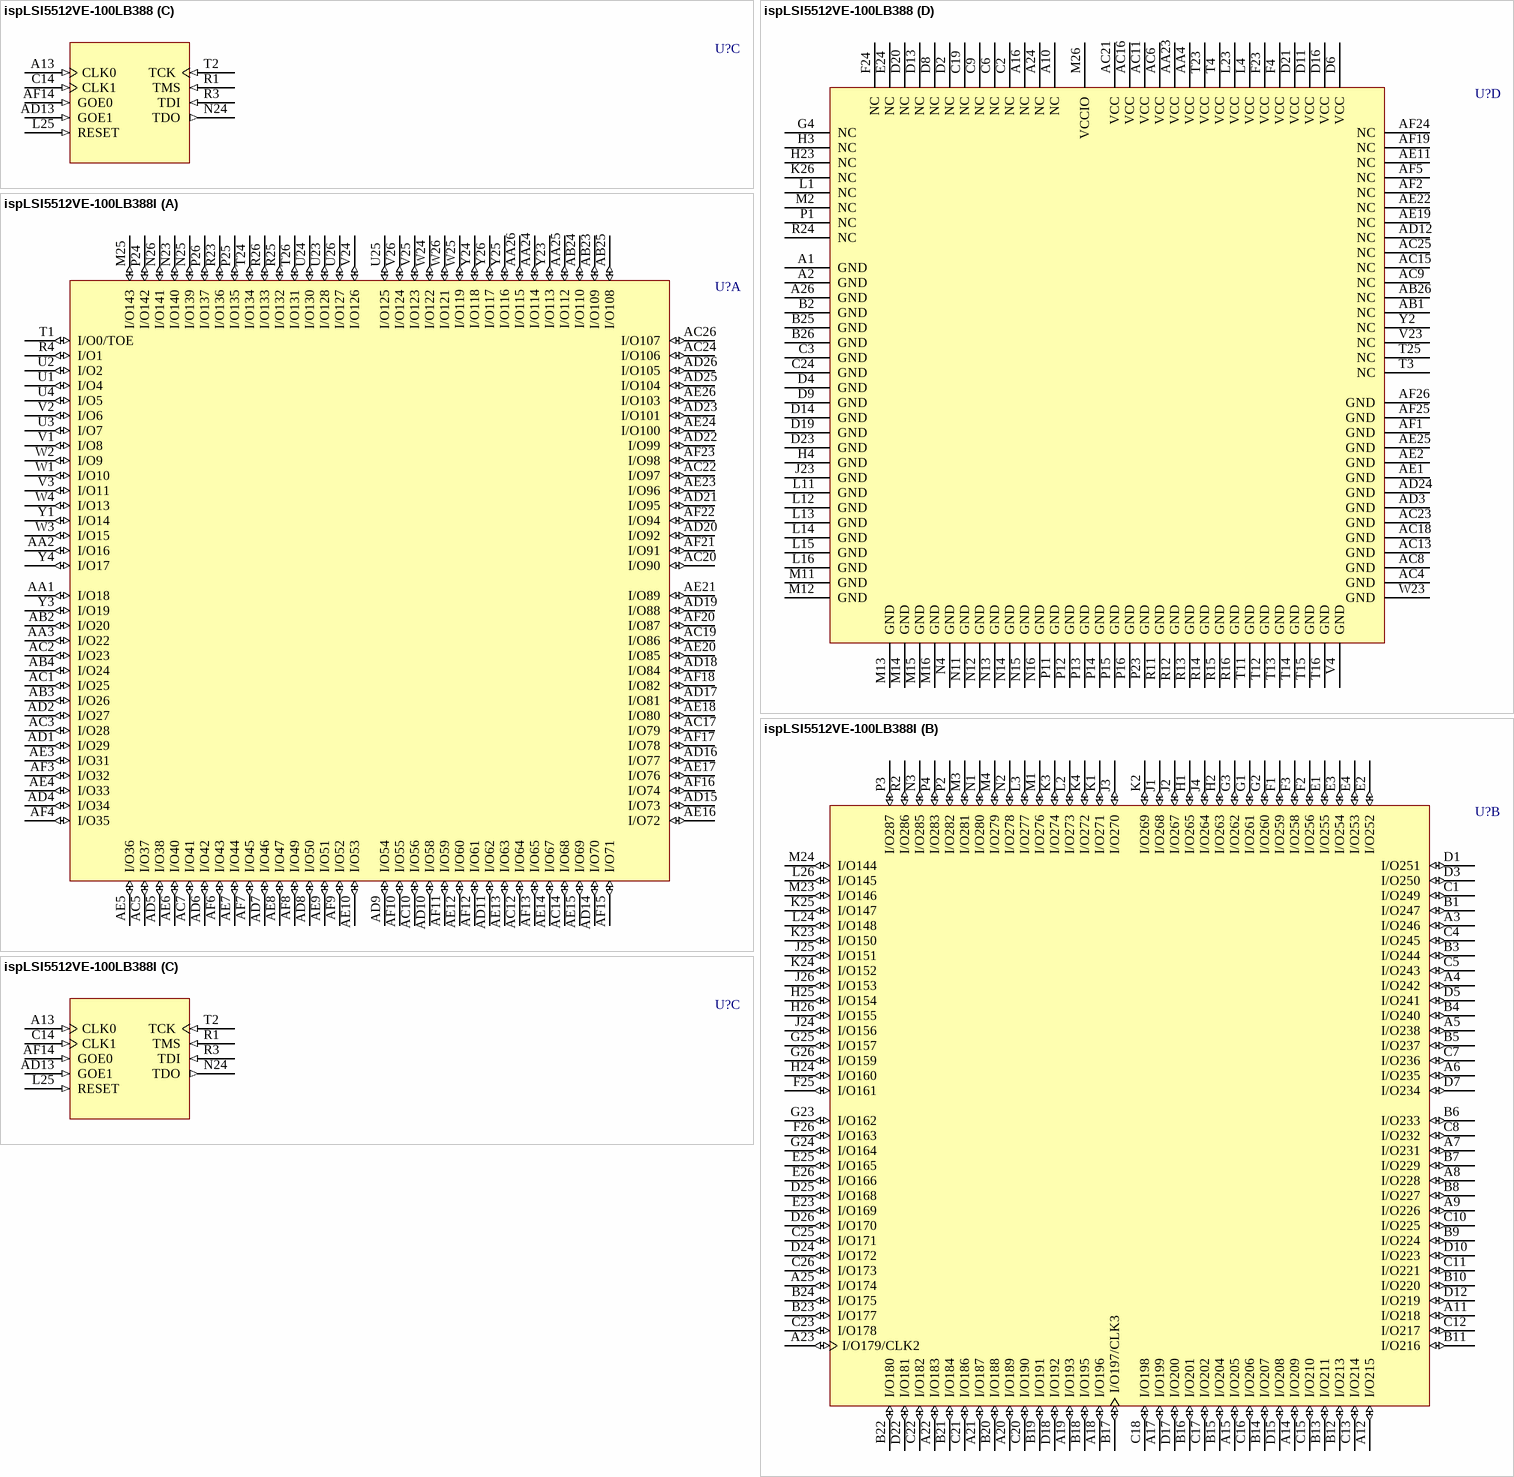
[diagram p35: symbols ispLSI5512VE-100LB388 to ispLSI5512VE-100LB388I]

## ispLSI5512VE-100LB388
designator U?
ispLSI 5512VE SuperWIDE High Density PLD with 256 User I/Os, 10 ns, 3.3 V, Commercial Grade
footprint BGA388 (BGA, 388-Leads, Body 35x35mm, Pitch 1.27mm)
3D model 5512VE-BGA388 (388-Ball Ball Grid Array (BGA388))
part A pins: AA1 I/O18 (io), AA2 I/O16 (io), AA3 I/O22 (io), AA24 I/O114 (io), AA25 I/O112 (io), AA26 I/O115 (io), AB2 I/O20 (io), AB3 I/O26 (io), AB4 I/O24 (io), AB23 I/O109 (io), AB24 I/O110 (io), AB25 I/O108 (io), AC1 I/O25 (io), AC2 I/O23 (io), AC3 I/O28 (io), AC5 I/O37 (io), AC7 I/O41 (io), AC10 I/O56 (io), AC12 I/O64 (io), AC14 I/O68 (io), AC17 I/O79 (io), AC19 I/O86 (io), AC20 I/O90 (io), AC22 I/O97 (io), AC24 I/O106 (io), AC26 I/O107 (io), AD1 I/O29 (io), AD2 I/O27 (io), AD4 I/O34 (io), AD5 I/O38 (io), AD6 I/O42 (io), AD7 I/O46 (io), AD8 I/O50 (io), AD9 I/O54 (io), AD10 I/O58 (io), AD11 I/O62 (io), AD14 I/O70 (io), AD15 I/O73 (io), AD16 I/O77 (io), AD17 I/O81 (io), AD18 I/O84 (io), AD19 I/O88 (io), AD20 I/O92 (io), AD21 I/O95 (io), AD22 I/O99 (io), AD23 I/O101 (io), AD25 I/O104 (io), AD26 I/O105 (io), AE3 I/O31 (io), AE4 I/O33 (io), AE5 I/O36 (io), AE6 I/O40 (io), AE7 I/O44 (io), AE8 I/O47 (io), AE9 I/O51 (io), AE10 I/O53 (io), AE12 I/O60 (io), AE13 I/O63 (io), AE14 I/O67 (io), AE15 I/O69 (io), AE16 I/O72 (io), AE17 I/O76 (io), AE18 I/O80 (io), AE20 I/O85 (io), AE21 I/O89 (io), AE23 I/O96 (io), AE24 I/O100 (io), AE26 I/O103 (io), AF3 I/O32 (io), AF4 I/O35 (io), AF6 I/O43 (io), AF7 I/O45 (io), AF8 I/O49 (io), AF9 I/O52 (io), AF10 I/O55 (io), AF11 I/O59 (io), AF12 I/O61 (io), AF13 I/O65 (io), AF15 I/O71 (io), AF16 I/O74 (io), AF17 I/O78 (io), AF18 I/O82 (io), AF20 I/O87 (io), AF21 I/O91 (io), AF22 I/O94 (io), AF23 I/O98 (io), M25 I/O143 (io), N23 I/O140 (io), N25 I/O139 (io), N26 I/O141 (io), P24 I/O142 (io), P25 I/O135 (io), P26 I/O137 (io), R4 I/O1 (io), R23 I/O136 (io), R25 I/O132 (io), R26 I/O133 (io), T1 I/O0/TOE (io), T24 I/O134 (io), T26 I/O131 (io), U1 I/O4 (io), U2 I/O2 (io), U3 I/O7 (io), U4 I/O5 (io), U23 I/O128 (io), U24 I/O130 (io), U25 I/O125 (io), U26 I/O127 (io), V1 I/O8 (io), V2 I/O6 (io), V3 I/O11 (io), V24 I/O126 (io), V25 I/O123 (io), V26 I/O124 (io), W1 I/O10 (io), W2 I/O9 (io), W3 I/O15 (io), W4 I/O13 (io), W24 I/O122 (io), W25 I/O119 (io), W26 I/O121 (io), Y1 I/O14 (io), Y3 I/O19 (io), Y4 I/O17 (io), Y23 I/O113 (io), Y24 I/O118 (io), Y25 I/O116 (io), Y26 I/O117 (io)
part B pins: A3 I/O246 (io), A4 I/O242 (io), A5 I/O238 (io), A6 I/O235 (io), A7 I/O231 (io), A8 I/O228 (io), A9 I/O226 (io), A11 I/O218 (io), A12 I/O215 (io), A14 I/O209 (io), A15 I/O205 (io), A17 I/O199 (io), A18 I/O196 (io), A19 I/O193 (io), A20 I/O189 (io), A21 I/O187 (io), A22 I/O183 (io), A23 I/O179/CLK2 (io), A25 I/O174 (io), B1 I/O247 (io), B3 I/O244 (io), B4 I/O240 (io), B5 I/O237 (io), B6 I/O233 (io), B7 I/O229 (io), B8 I/O227 (io), B9 I/O224 (io), B10 I/O220 (io), B11 I/O216 (io), B12 I/O213 (io), B13 I/O211 (io), B14 I/O207 (io), B15 I/O204 (io), B16 I/O201 (io), B17 I/O197/CLK3 (io), B18 I/O195 (io), B19 I/O191 (io), B20 I/O188 (io), B21 I/O184 (io), B22 I/O180 (io), B23 I/O177 (io), B24 I/O175 (io), C1 I/O249 (io), C4 I/O245 (io), C5 I/O243 (io), C7 I/O236 (io), C8 I/O232 (io), C10 I/O225 (io), C11 I/O221 (io), C12 I/O217 (io), C13 I/O214 (io), C15 I/O210 (io), C16 I/O206 (io), C17 I/O202 (io), C18 I/O198 (io), C20 I/O190 (io), C21 I/O186 (io), C22 I/O182 (io), C23 I/O178 (io), C25 I/O171 (io), C26 I/O173 (io), D1 I/O251 (io), D3 I/O250 (io), D5 I/O241 (io), D7 I/O234 (io), D10 I/O223 (io), D12 I/O219 (io), D15 I/O208 (io), D17 I/O200 (io), D18 I/O192 (io), D22 I/O181 (io), D24 I/O172 (io), D25 I/O168 (io), D26 I/O170 (io), E1 I/O255 (io), E2 I/O252 (io), E3 I/O254 (io), E4 I/O253 (io), E23 I/O169 (io), E25 I/O165 (io), E26 I/O166 (io), F1 I/O259 (io), F2 I/O256 (io), F3 I/O258 (io), F25 I/O161 (io), F26 I/O163 (io), G1 I/O261 (io), G2 I/O260 (io), G3 I/O262 (io), G23 I/O162 (io), G24 I/O164 (io), G25 I/O157 (io), G26 I/O159 (io), H1 I/O265 (io), H2 I/O263 (io), H24 I/O160 (io), H25 I/O154 (io), H26 I/O155 (io), J1 I/O268 (io), J2 I/O267 (io), J3 I/O270 (io), J4 I/O264 (io), J24 I/O156 (io), J25 I/O151 (io), J26 I/O153 (io), K1 I/O271 (io), K2 I/O269 (io), K3 I/O274 (io), K4 I/O272 (io), K23 I/O150 (io), K24 I/O152 (io), K25 I/O147 (io), L2 I/O273 (io), L3 I/O277 (io), L24 I/O148 (io), L26 I/O145 (io), M1 I/O276 (io), M3 I/O281 (io), M4 I/O279 (io), M23 I/O146 (io), M24 I/O144 (io), N1 I/O280 (io), N2 I/O278 (io), N3 I/O285 (io), P2 I/O282 (io), P3 I/O287 (io), P4 I/O283 (io), R2 I/O286 (io)
part C pins: A13 CLK0 (in), AD13 GOE1 (in), AF14 GOE0 (in), C14 CLK1 (in), L25 RESET (in), N24 TDO (out), R1 TMS (in), R3 TDI (in), T2 TCK (in)
part D pins: A1 GND (power), A2 GND (power), A10 NC, A16 NC, A24 NC, A26 GND (power), AA4 VCC (power), AA23 VCC (power), AB1 NC, AB26 NC, AC4 GND (power), AC6 VCC (power), AC8 GND (power), AC9 NC, AC11 VCC (power), AC13 GND (power), AC15 NC, AC16 VCC (power), AC18 GND (power), AC21 VCC (power), AC23 GND (power), AC25 NC, AD3 GND (power), AD12 NC, AD24 GND (power), AE1 GND (power), AE2 GND (power), AE11 NC, AE19 NC, AE22 NC, AE25 GND (power), AF1 GND (power), AF2 NC, AF5 NC, AF19 NC, AF24 NC, AF25 GND (power), AF26 GND (power), B2 GND (power), B25 GND (power), B26 GND (power), C2 NC, C3 GND (power), C6 NC, C9 NC, C19 NC, C24 GND (power), D2 NC, D4 GND (power), D6 VCC (power), D8 NC, D9 GND (power), D11 VCC (power), D13 NC, D14 GND (power), D16 VCC (power), D19 GND (power), D20 NC, D21 VCC (power), D23 GND (power), E24 NC, F4 VCC (power), F23 VCC (power), F24 NC, G4 NC, H3 NC, H4 GND (power), H23 NC, J23 GND (power), K26 NC, L1 NC, L4 VCC (power), L11 GND (power), L12 GND (power), L13 GND (power), L14 GND (power), L15 GND (power), L16 GND (power), L23 VCC (power), M2 NC, M11 GND (power), M12 GND (power), M13 GND (power), M14 GND (power), M15 GND (power), M16 GND (power), M26 VCCIO (power), N4 GND (power), N11 GND (power), N12 GND (power), N13 GND (power), N14 GND (power), N15 GND (power), N16 GND (power), P1 NC, P11 GND (power), P12 GND (power), P13 GND (power), P14 GND (power), P15 GND (power), P16 GND (power), P23 GND (power), R11 GND (power), R12 GND (power), R13 GND (power), R14 GND (power), R15 GND (power), R16 GND (power), R24 NC, T3 NC, T4 VCC (power), T11 GND (power), T12 GND (power), T13 GND (power), T14 GND (power), T15 GND (power), T16 GND (power), T23 VCC (power), T25 NC, V4 GND (power), V23 NC, W23 GND (power), Y2 NC

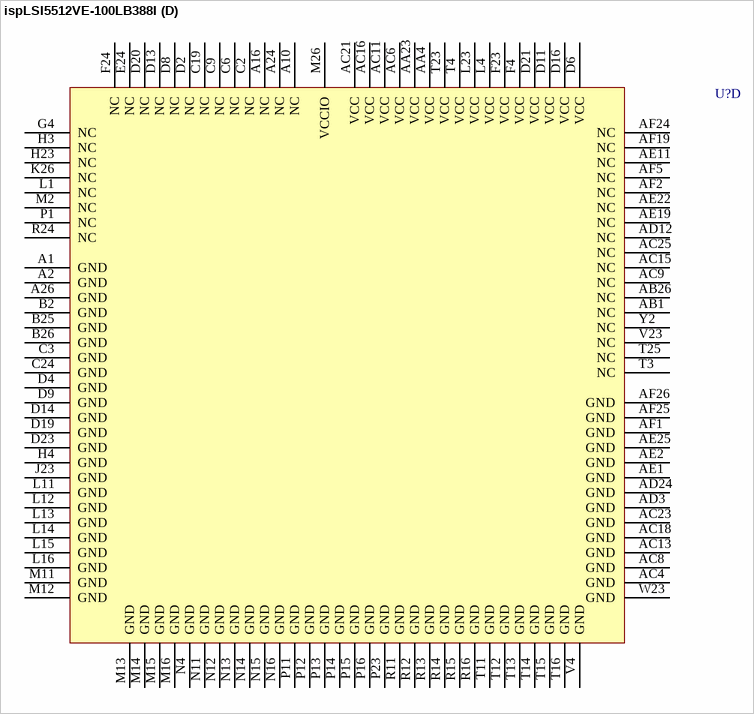
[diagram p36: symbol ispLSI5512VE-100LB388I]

## ispLSI5512VE-100LB388I
designator U?
ispLSI 5512VE SuperWIDE High Density PLD with 256 User I/Os, 10 ns, 3.3 V, Industrial Grade
footprint BGA388 (BGA, 388-Leads, Body 35x35mm, Pitch 1.27mm)
3D model 5512VE-BGA388 (388-Ball Ball Grid Array (BGA388))
part A pins: AA1 I/O18 (io), AA2 I/O16 (io), AA3 I/O22 (io), AA24 I/O114 (io), AA25 I/O112 (io), AA26 I/O115 (io), AB2 I/O20 (io), AB3 I/O26 (io), AB4 I/O24 (io), AB23 I/O109 (io), AB24 I/O110 (io), AB25 I/O108 (io), AC1 I/O25 (io), AC2 I/O23 (io), AC3 I/O28 (io), AC5 I/O37 (io), AC7 I/O41 (io), AC10 I/O56 (io), AC12 I/O64 (io), AC14 I/O68 (io), AC17 I/O79 (io), AC19 I/O86 (io), AC20 I/O90 (io), AC22 I/O97 (io), AC24 I/O106 (io), AC26 I/O107 (io), AD1 I/O29 (io), AD2 I/O27 (io), AD4 I/O34 (io), AD5 I/O38 (io), AD6 I/O42 (io), AD7 I/O46 (io), AD8 I/O50 (io), AD9 I/O54 (io), AD10 I/O58 (io), AD11 I/O62 (io), AD14 I/O70 (io), AD15 I/O73 (io), AD16 I/O77 (io), AD17 I/O81 (io), AD18 I/O84 (io), AD19 I/O88 (io), AD20 I/O92 (io), AD21 I/O95 (io), AD22 I/O99 (io), AD23 I/O101 (io), AD25 I/O104 (io), AD26 I/O105 (io), AE3 I/O31 (io), AE4 I/O33 (io), AE5 I/O36 (io), AE6 I/O40 (io), AE7 I/O44 (io), AE8 I/O47 (io), AE9 I/O51 (io), AE10 I/O53 (io), AE12 I/O60 (io), AE13 I/O63 (io), AE14 I/O67 (io), AE15 I/O69 (io), AE16 I/O72 (io), AE17 I/O76 (io), AE18 I/O80 (io), AE20 I/O85 (io), AE21 I/O89 (io), AE23 I/O96 (io), AE24 I/O100 (io), AE26 I/O103 (io), AF3 I/O32 (io), AF4 I/O35 (io), AF6 I/O43 (io), AF7 I/O45 (io), AF8 I/O49 (io), AF9 I/O52 (io), AF10 I/O55 (io), AF11 I/O59 (io), AF12 I/O61 (io), AF13 I/O65 (io), AF15 I/O71 (io), AF16 I/O74 (io), AF17 I/O78 (io), AF18 I/O82 (io), AF20 I/O87 (io), AF21 I/O91 (io), AF22 I/O94 (io), AF23 I/O98 (io), M25 I/O143 (io), N23 I/O140 (io), N25 I/O139 (io), N26 I/O141 (io), P24 I/O142 (io), P25 I/O135 (io), P26 I/O137 (io), R4 I/O1 (io), R23 I/O136 (io), R25 I/O132 (io), R26 I/O133 (io), T1 I/O0/TOE (io), T24 I/O134 (io), T26 I/O131 (io), U1 I/O4 (io), U2 I/O2 (io), U3 I/O7 (io), U4 I/O5 (io), U23 I/O128 (io), U24 I/O130 (io), U25 I/O125 (io), U26 I/O127 (io), V1 I/O8 (io), V2 I/O6 (io), V3 I/O11 (io), V24 I/O126 (io), V25 I/O123 (io), V26 I/O124 (io), W1 I/O10 (io), W2 I/O9 (io), W3 I/O15 (io), W4 I/O13 (io), W24 I/O122 (io), W25 I/O119 (io), W26 I/O121 (io), Y1 I/O14 (io), Y3 I/O19 (io), Y4 I/O17 (io), Y23 I/O113 (io), Y24 I/O118 (io), Y25 I/O116 (io), Y26 I/O117 (io)
part B pins: A3 I/O246 (io), A4 I/O242 (io), A5 I/O238 (io), A6 I/O235 (io), A7 I/O231 (io), A8 I/O228 (io), A9 I/O226 (io), A11 I/O218 (io), A12 I/O215 (io), A14 I/O209 (io), A15 I/O205 (io), A17 I/O199 (io), A18 I/O196 (io), A19 I/O193 (io), A20 I/O189 (io), A21 I/O187 (io), A22 I/O183 (io), A23 I/O179/CLK2 (io), A25 I/O174 (io), B1 I/O247 (io), B3 I/O244 (io), B4 I/O240 (io), B5 I/O237 (io), B6 I/O233 (io), B7 I/O229 (io), B8 I/O227 (io), B9 I/O224 (io), B10 I/O220 (io), B11 I/O216 (io), B12 I/O213 (io), B13 I/O211 (io), B14 I/O207 (io), B15 I/O204 (io), B16 I/O201 (io), B17 I/O197/CLK3 (io), B18 I/O195 (io), B19 I/O191 (io), B20 I/O188 (io), B21 I/O184 (io), B22 I/O180 (io), B23 I/O177 (io), B24 I/O175 (io), C1 I/O249 (io), C4 I/O245 (io), C5 I/O243 (io), C7 I/O236 (io), C8 I/O232 (io), C10 I/O225 (io), C11 I/O221 (io), C12 I/O217 (io), C13 I/O214 (io), C15 I/O210 (io), C16 I/O206 (io), C17 I/O202 (io), C18 I/O198 (io), C20 I/O190 (io), C21 I/O186 (io), C22 I/O182 (io), C23 I/O178 (io), C25 I/O171 (io), C26 I/O173 (io), D1 I/O251 (io), D3 I/O250 (io), D5 I/O241 (io), D7 I/O234 (io), D10 I/O223 (io), D12 I/O219 (io), D15 I/O208 (io), D17 I/O200 (io), D18 I/O192 (io), D22 I/O181 (io), D24 I/O172 (io), D25 I/O168 (io), D26 I/O170 (io), E1 I/O255 (io), E2 I/O252 (io), E3 I/O254 (io), E4 I/O253 (io), E23 I/O169 (io), E25 I/O165 (io), E26 I/O166 (io), F1 I/O259 (io), F2 I/O256 (io), F3 I/O258 (io), F25 I/O161 (io), F26 I/O163 (io), G1 I/O261 (io), G2 I/O260 (io), G3 I/O262 (io), G23 I/O162 (io), G24 I/O164 (io), G25 I/O157 (io), G26 I/O159 (io), H1 I/O265 (io), H2 I/O263 (io), H24 I/O160 (io), H25 I/O154 (io), H26 I/O155 (io), J1 I/O268 (io), J2 I/O267 (io), J3 I/O270 (io), J4 I/O264 (io), J24 I/O156 (io), J25 I/O151 (io), J26 I/O153 (io), K1 I/O271 (io), K2 I/O269 (io), K3 I/O274 (io), K4 I/O272 (io), K23 I/O150 (io), K24 I/O152 (io), K25 I/O147 (io), L2 I/O273 (io), L3 I/O277 (io), L24 I/O148 (io), L26 I/O145 (io), M1 I/O276 (io), M3 I/O281 (io), M4 I/O279 (io), M23 I/O146 (io), M24 I/O144 (io), N1 I/O280 (io), N2 I/O278 (io), N3 I/O285 (io), P2 I/O282 (io), P3 I/O287 (io), P4 I/O283 (io), R2 I/O286 (io)
part C pins: A13 CLK0 (in), AD13 GOE1 (in), AF14 GOE0 (in), C14 CLK1 (in), L25 RESET (in), N24 TDO (out), R1 TMS (in), R3 TDI (in), T2 TCK (in)
part D pins: A1 GND (power), A2 GND (power), A10 NC, A16 NC, A24 NC, A26 GND (power), AA4 VCC (power), AA23 VCC (power), AB1 NC, AB26 NC, AC4 GND (power), AC6 VCC (power), AC8 GND (power), AC9 NC, AC11 VCC (power), AC13 GND (power), AC15 NC, AC16 VCC (power), AC18 GND (power), AC21 VCC (power), AC23 GND (power), AC25 NC, AD3 GND (power), AD12 NC, AD24 GND (power), AE1 GND (power), AE2 GND (power), AE11 NC, AE19 NC, AE22 NC, AE25 GND (power), AF1 GND (power), AF2 NC, AF5 NC, AF19 NC, AF24 NC, AF25 GND (power), AF26 GND (power), B2 GND (power), B25 GND (power), B26 GND (power), C2 NC, C3 GND (power), C6 NC, C9 NC, C19 NC, C24 GND (power), D2 NC, D4 GND (power), D6 VCC (power), D8 NC, D9 GND (power), D11 VCC (power), D13 NC, D14 GND (power), D16 VCC (power), D19 GND (power), D20 NC, D21 VCC (power), D23 GND (power), E24 NC, F4 VCC (power), F23 VCC (power), F24 NC, G4 NC, H3 NC, H4 GND (power), H23 NC, J23 GND (power), K26 NC, L1 NC, L4 VCC (power), L11 GND (power), L12 GND (power), L13 GND (power), L14 GND (power), L15 GND (power), L16 GND (power), L23 VCC (power), M2 NC, M11 GND (power), M12 GND (power), M13 GND (power), M14 GND (power), M15 GND (power), M16 GND (power), M26 VCCIO (power), N4 GND (power), N11 GND (power), N12 GND (power), N13 GND (power), N14 GND (power), N15 GND (power), N16 GND (power), P1 NC, P11 GND (power), P12 GND (power), P13 GND (power), P14 GND (power), P15 GND (power), P16 GND (power), P23 GND (power), R11 GND (power), R12 GND (power), R13 GND (power), R14 GND (power), R15 GND (power), R16 GND (power), R24 NC, T3 NC, T4 VCC (power), T11 GND (power), T12 GND (power), T13 GND (power), T14 GND (power), T15 GND (power), T16 GND (power), T23 VCC (power), T25 NC, V4 GND (power), V23 NC, W23 GND (power), Y2 NC

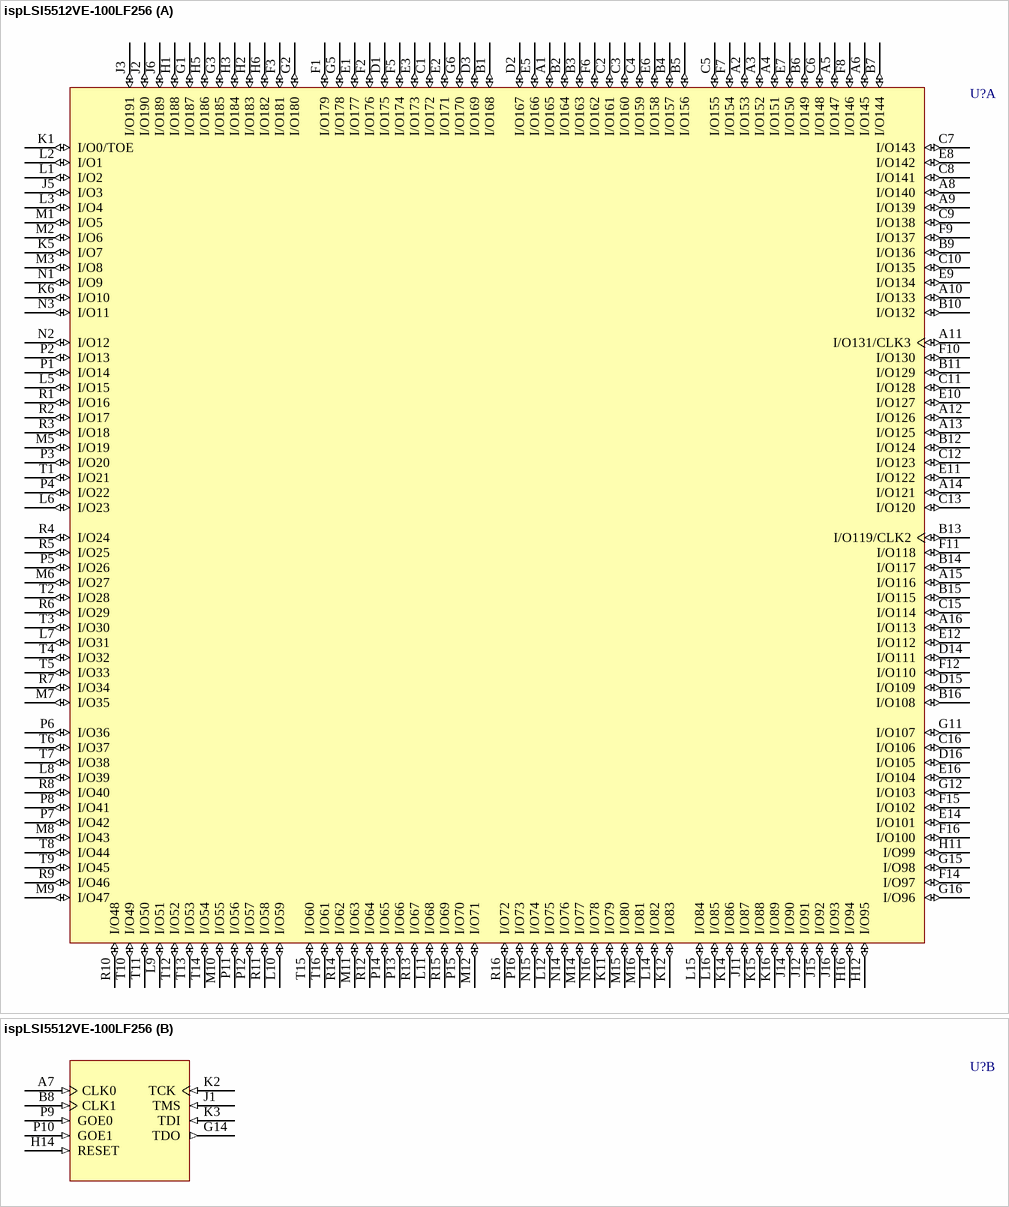
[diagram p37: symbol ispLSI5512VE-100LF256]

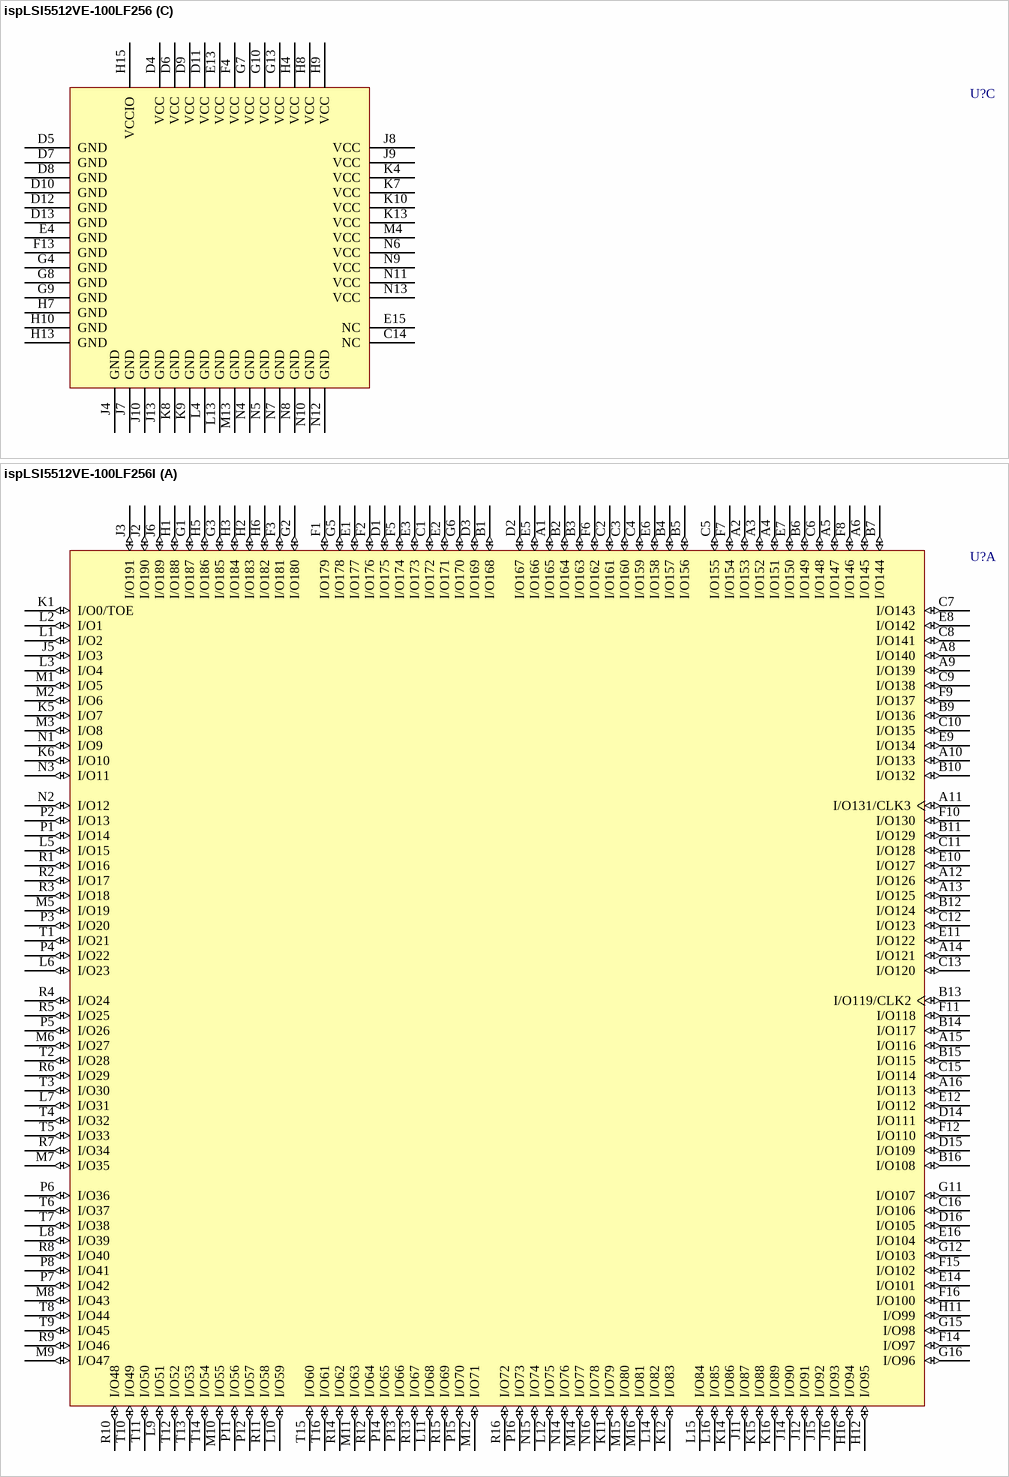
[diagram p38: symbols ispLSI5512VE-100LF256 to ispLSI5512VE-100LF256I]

## ispLSI5512VE-100LF256
designator U?
ispLSI 5512VE SuperWIDE High Density PLD with 192 User I/Os, 10 ns, 3.3 V, Commercial Grade
footprint fpBGA256 (BGA, 256-Leads, Body 17x17mm, Pitch 1mm)
3D model 5512VE-fpBGA256 (256-Ball Fine Pitch Ball Grid Array (fpBGA256))
part A pins: A1 I/O165 (io), A2 I/O153 (io), A3 I/O152 (io), A4 I/O151 (io), A5 I/O147 (io), A6 I/O145 (io), A8 I/O140 (io), A9 I/O139 (io), A10 I/O133 (io), A11 I/O131/CLK3 (io), A12 I/O126 (io), A13 I/O125 (io), A14 I/O121 (io), A15 I/O116 (io), A16 I/O113 (io), B1 I/O168 (io), B2 I/O164 (io), B3 I/O163 (io), B4 I/O157 (io), B5 I/O156 (io), B6 I/O149 (io), B7 I/O144 (io), B9 I/O136 (io), B10 I/O132 (io), B11 I/O129 (io), B12 I/O124 (io), B13 I/O119/CLK2 (io), B14 I/O117 (io), B15 I/O115 (io), B16 I/O108 (io), C1 I/O172 (io), C2 I/O161 (io), C3 I/O160 (io), C4 I/O159 (io), C5 I/O155 (io), C6 I/O148 (io), C7 I/O143 (io), C8 I/O141 (io), C9 I/O138 (io), C10 I/O135 (io), C11 I/O128 (io), C12 I/O123 (io), C13 I/O120 (io), C15 I/O114 (io), C16 I/O106 (io), D1 I/O175 (io), D2 I/O167 (io), D3 I/O169 (io), D14 I/O111 (io), D15 I/O109 (io), D16 I/O105 (io), E1 I/O177 (io), E2 I/O171 (io), E3 I/O173 (io), E5 I/O166 (io), E6 I/O158 (io), E7 I/O150 (io), E8 I/O142 (io), E9 I/O134 (io), E10 I/O127 (io), E11 I/O122 (io), E12 I/O112 (io), E14 I/O101 (io), E16 I/O104 (io), F1 I/O179 (io), F2 I/O176 (io), F3 I/O181 (io), F5 I/O174 (io), F6 I/O162 (io), F7 I/O154 (io), F8 I/O146 (io), F9 I/O137 (io), F10 I/O130 (io), F11 I/O118 (io), F12 I/O110 (io), F14 I/O97 (io), F15 I/O102 (io), F16 I/O100 (io), G1 I/O187 (io), G2 I/O180 (io), G3 I/O185 (io), G5 I/O178 (io), G6 I/O170 (io), G11 I/O107 (io), G12 I/O103 (io), G15 I/O98 (io), G16 I/O96 (io), H1 I/O188 (io), H2 I/O183 (io), H3 I/O184 (io), H5 I/O186 (io), H6 I/O182 (io), H11 I/O99 (io), H12 I/O95 (io), H16 I/O94 (io), J2 I/O190 (io), J3 I/O191 (io), J5 I/O3 (io), J6 I/O189 (io), J11 I/O87 (io), J12 I/O91 (io), J14 I/O90 (io), J15 I/O92 (io), J16 I/O93 (io), K1 I/O0/TOE (io), K5 I/O7 (io), K6 I/O10 (io), K11 I/O79 (io), K12 I/O83 (io), K14 I/O86 (io), K15 I/O88 (io), K16 I/O89 (io), L1 I/O2 (io), L2 I/O1 (io), L3 I/O4 (io), L5 I/O15 (io), L6 I/O23 (io), L7 I/O31 (io), L8 I/O39 (io), L9 I/O51 (io), L10 I/O59 (io), L11 I/O68 (io), L12 I/O75 (io), L14 I/O82 (io), L15 I/O84 (io), L16 I/O85 (io), M1 I/O5 (io), M2 I/O6 (io), M3 I/O8 (io), M5 I/O19 (io), M6 I/O27 (io), M7 I/O35 (io), M8 I/O43 (io), M9 I/O47 (io), M10 I/O55 (io), M11 I/O63 (io), M12 I/O71 (io), M14 I/O77 (io), M15 I/O80 (io), M16 I/O81 (io), N1 I/O9 (io), N2 I/O12 (io), N3 I/O11 (io), N14 I/O76 (io), N15 I/O74 (io), N16 I/O78 (io), P1 I/O14 (io), P2 I/O13 (io), P3 I/O20 (io), P4 I/O22 (io), P5 I/O26 (io), P6 I/O36 (io), P7 I/O42 (io), P8 I/O41 (io), P11 I/O56 (io), P12 I/O57 (io), P13 I/O66 (io), P14 I/O65 (io), P15 I/O70 (io), P16 I/O73 (io), R1 I/O16 (io), R2 I/O17 (io), R3 I/O18 (io), R4 I/O24 (io), R5 I/O25 (io), R6 I/O29 (io), R7 I/O34 (io), R8 I/O40 (io), R9 I/O46 (io), R10 I/O48 (io), R11 I/O58 (io), R12 I/O64 (io), R13 I/O67 (io), R14 I/O62 (io), R15 I/O69 (io), R16 I/O72 (io), T1 I/O21 (io), T2 I/O28 (io), T3 I/O30 (io), T4 I/O32 (io), T5 I/O33 (io), T6 I/O37 (io), T7 I/O38 (io), T8 I/O44 (io), T9 I/O45 (io), T10 I/O49 (io), T11 I/O50 (io), T12 I/O52 (io), T13 I/O53 (io), T14 I/O54 (io), T15 I/O60 (io), T16 I/O61 (io)
part B pins: A7 CLK0 (in), B8 CLK1 (in), G14 TDO (out), H14 RESET (in), J1 TMS (in), K2 TCK (in), K3 TDI (in), P9 GOE0 (in), P10 GOE1 (in)
part C pins: C14 NC, D4 VCC (power), D5 GND (power), D6 VCC (power), D7 GND (power), D8 GND (power), D9 VCC (power), D10 GND (power), D11 VCC (power), D12 GND (power), D13 GND (power), E4 GND (power), E13 VCC (power), E15 NC, F4 VCC (power), F13 GND (power), G4 GND (power), G7 VCC (power), G8 GND (power), G9 GND (power), G10 VCC (power), G13 VCC (power), H4 VCC (power), H7 GND (power), H8 VCC (power), H9 VCC (power), H10 GND (power), H13 GND (power), H15 VCCIO (power), J4 GND (power), J7 GND (power), J8 VCC (power), J9 VCC (power), J10 GND (power), J13 GND (power), K4 VCC (power), K7 VCC (power), K8 GND (power), K9 GND (power), K10 VCC (power), K13 VCC (power), L4 GND (power), L13 GND (power), M4 VCC (power), M13 GND (power), N4 GND (power), N5 GND (power), N6 VCC (power), N7 GND (power), N8 GND (power), N9 VCC (power), N10 GND (power), N11 VCC (power), N12 GND (power), N13 VCC (power)

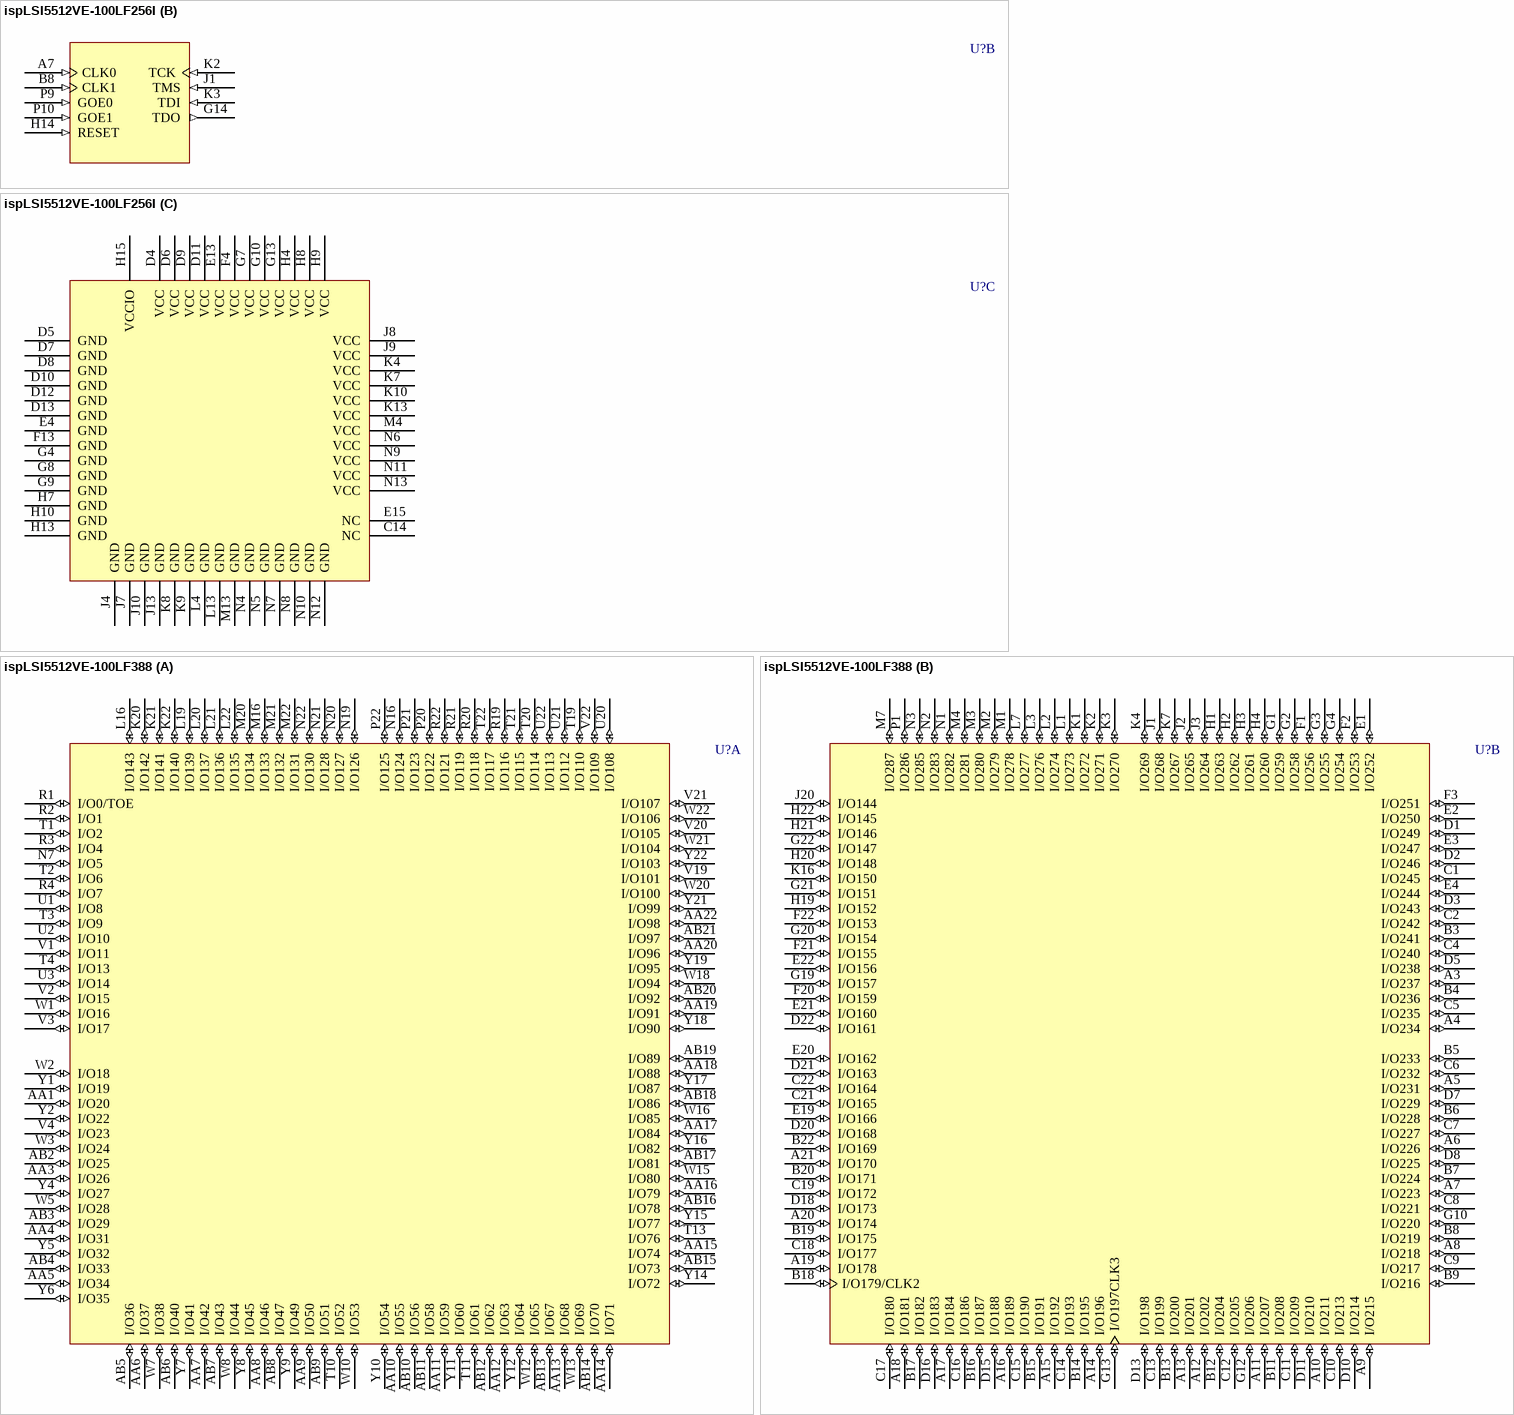
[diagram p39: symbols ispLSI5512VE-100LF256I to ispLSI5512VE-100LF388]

## ispLSI5512VE-100LF256I
designator U?
ispLSI 5512VE SuperWIDE High Density PLD with 192 User I/Os, 10 ns, 3.3 V, Industrial Grade
footprint fpBGA256 (BGA, 256-Leads, Body 17x17mm, Pitch 1mm)
3D model 5512VE-fpBGA256 (256-Ball Fine Pitch Ball Grid Array (fpBGA256))
part A pins: A1 I/O165 (io), A2 I/O153 (io), A3 I/O152 (io), A4 I/O151 (io), A5 I/O147 (io), A6 I/O145 (io), A8 I/O140 (io), A9 I/O139 (io), A10 I/O133 (io), A11 I/O131/CLK3 (io), A12 I/O126 (io), A13 I/O125 (io), A14 I/O121 (io), A15 I/O116 (io), A16 I/O113 (io), B1 I/O168 (io), B2 I/O164 (io), B3 I/O163 (io), B4 I/O157 (io), B5 I/O156 (io), B6 I/O149 (io), B7 I/O144 (io), B9 I/O136 (io), B10 I/O132 (io), B11 I/O129 (io), B12 I/O124 (io), B13 I/O119/CLK2 (io), B14 I/O117 (io), B15 I/O115 (io), B16 I/O108 (io), C1 I/O172 (io), C2 I/O161 (io), C3 I/O160 (io), C4 I/O159 (io), C5 I/O155 (io), C6 I/O148 (io), C7 I/O143 (io), C8 I/O141 (io), C9 I/O138 (io), C10 I/O135 (io), C11 I/O128 (io), C12 I/O123 (io), C13 I/O120 (io), C15 I/O114 (io), C16 I/O106 (io), D1 I/O175 (io), D2 I/O167 (io), D3 I/O169 (io), D14 I/O111 (io), D15 I/O109 (io), D16 I/O105 (io), E1 I/O177 (io), E2 I/O171 (io), E3 I/O173 (io), E5 I/O166 (io), E6 I/O158 (io), E7 I/O150 (io), E8 I/O142 (io), E9 I/O134 (io), E10 I/O127 (io), E11 I/O122 (io), E12 I/O112 (io), E14 I/O101 (io), E16 I/O104 (io), F1 I/O179 (io), F2 I/O176 (io), F3 I/O181 (io), F5 I/O174 (io), F6 I/O162 (io), F7 I/O154 (io), F8 I/O146 (io), F9 I/O137 (io), F10 I/O130 (io), F11 I/O118 (io), F12 I/O110 (io), F14 I/O97 (io), F15 I/O102 (io), F16 I/O100 (io), G1 I/O187 (io), G2 I/O180 (io), G3 I/O185 (io), G5 I/O178 (io), G6 I/O170 (io), G11 I/O107 (io), G12 I/O103 (io), G15 I/O98 (io), G16 I/O96 (io), H1 I/O188 (io), H2 I/O183 (io), H3 I/O184 (io), H5 I/O186 (io), H6 I/O182 (io), H11 I/O99 (io), H12 I/O95 (io), H16 I/O94 (io), J2 I/O190 (io), J3 I/O191 (io), J5 I/O3 (io), J6 I/O189 (io), J11 I/O87 (io), J12 I/O91 (io), J14 I/O90 (io), J15 I/O92 (io), J16 I/O93 (io), K1 I/O0/TOE (io), K5 I/O7 (io), K6 I/O10 (io), K11 I/O79 (io), K12 I/O83 (io), K14 I/O86 (io), K15 I/O88 (io), K16 I/O89 (io), L1 I/O2 (io), L2 I/O1 (io), L3 I/O4 (io), L5 I/O15 (io), L6 I/O23 (io), L7 I/O31 (io), L8 I/O39 (io), L9 I/O51 (io), L10 I/O59 (io), L11 I/O68 (io), L12 I/O75 (io), L14 I/O82 (io), L15 I/O84 (io), L16 I/O85 (io), M1 I/O5 (io), M2 I/O6 (io), M3 I/O8 (io), M5 I/O19 (io), M6 I/O27 (io), M7 I/O35 (io), M8 I/O43 (io), M9 I/O47 (io), M10 I/O55 (io), M11 I/O63 (io), M12 I/O71 (io), M14 I/O77 (io), M15 I/O80 (io), M16 I/O81 (io), N1 I/O9 (io), N2 I/O12 (io), N3 I/O11 (io), N14 I/O76 (io), N15 I/O74 (io), N16 I/O78 (io), P1 I/O14 (io), P2 I/O13 (io), P3 I/O20 (io), P4 I/O22 (io), P5 I/O26 (io), P6 I/O36 (io), P7 I/O42 (io), P8 I/O41 (io), P11 I/O56 (io), P12 I/O57 (io), P13 I/O66 (io), P14 I/O65 (io), P15 I/O70 (io), P16 I/O73 (io), R1 I/O16 (io), R2 I/O17 (io), R3 I/O18 (io), R4 I/O24 (io), R5 I/O25 (io), R6 I/O29 (io), R7 I/O34 (io), R8 I/O40 (io), R9 I/O46 (io), R10 I/O48 (io), R11 I/O58 (io), R12 I/O64 (io), R13 I/O67 (io), R14 I/O62 (io), R15 I/O69 (io), R16 I/O72 (io), T1 I/O21 (io), T2 I/O28 (io), T3 I/O30 (io), T4 I/O32 (io), T5 I/O33 (io), T6 I/O37 (io), T7 I/O38 (io), T8 I/O44 (io), T9 I/O45 (io), T10 I/O49 (io), T11 I/O50 (io), T12 I/O52 (io), T13 I/O53 (io), T14 I/O54 (io), T15 I/O60 (io), T16 I/O61 (io)
part B pins: A7 CLK0 (in), B8 CLK1 (in), G14 TDO (out), H14 RESET (in), J1 TMS (in), K2 TCK (in), K3 TDI (in), P9 GOE0 (in), P10 GOE1 (in)
part C pins: C14 NC, D4 VCC (power), D5 GND (power), D6 VCC (power), D7 GND (power), D8 GND (power), D9 VCC (power), D10 GND (power), D11 VCC (power), D12 GND (power), D13 GND (power), E4 GND (power), E13 VCC (power), E15 NC, F4 VCC (power), F13 GND (power), G4 GND (power), G7 VCC (power), G8 GND (power), G9 GND (power), G10 VCC (power), G13 VCC (power), H4 VCC (power), H7 GND (power), H8 VCC (power), H9 VCC (power), H10 GND (power), H13 GND (power), H15 VCCIO (power), J4 GND (power), J7 GND (power), J8 VCC (power), J9 VCC (power), J10 GND (power), J13 GND (power), K4 VCC (power), K7 VCC (power), K8 GND (power), K9 GND (power), K10 VCC (power), K13 VCC (power), L4 GND (power), L13 GND (power), M4 VCC (power), M13 GND (power), N4 GND (power), N5 GND (power), N6 VCC (power), N7 GND (power), N8 GND (power), N9 VCC (power), N10 GND (power), N11 VCC (power), N12 GND (power), N13 VCC (power)

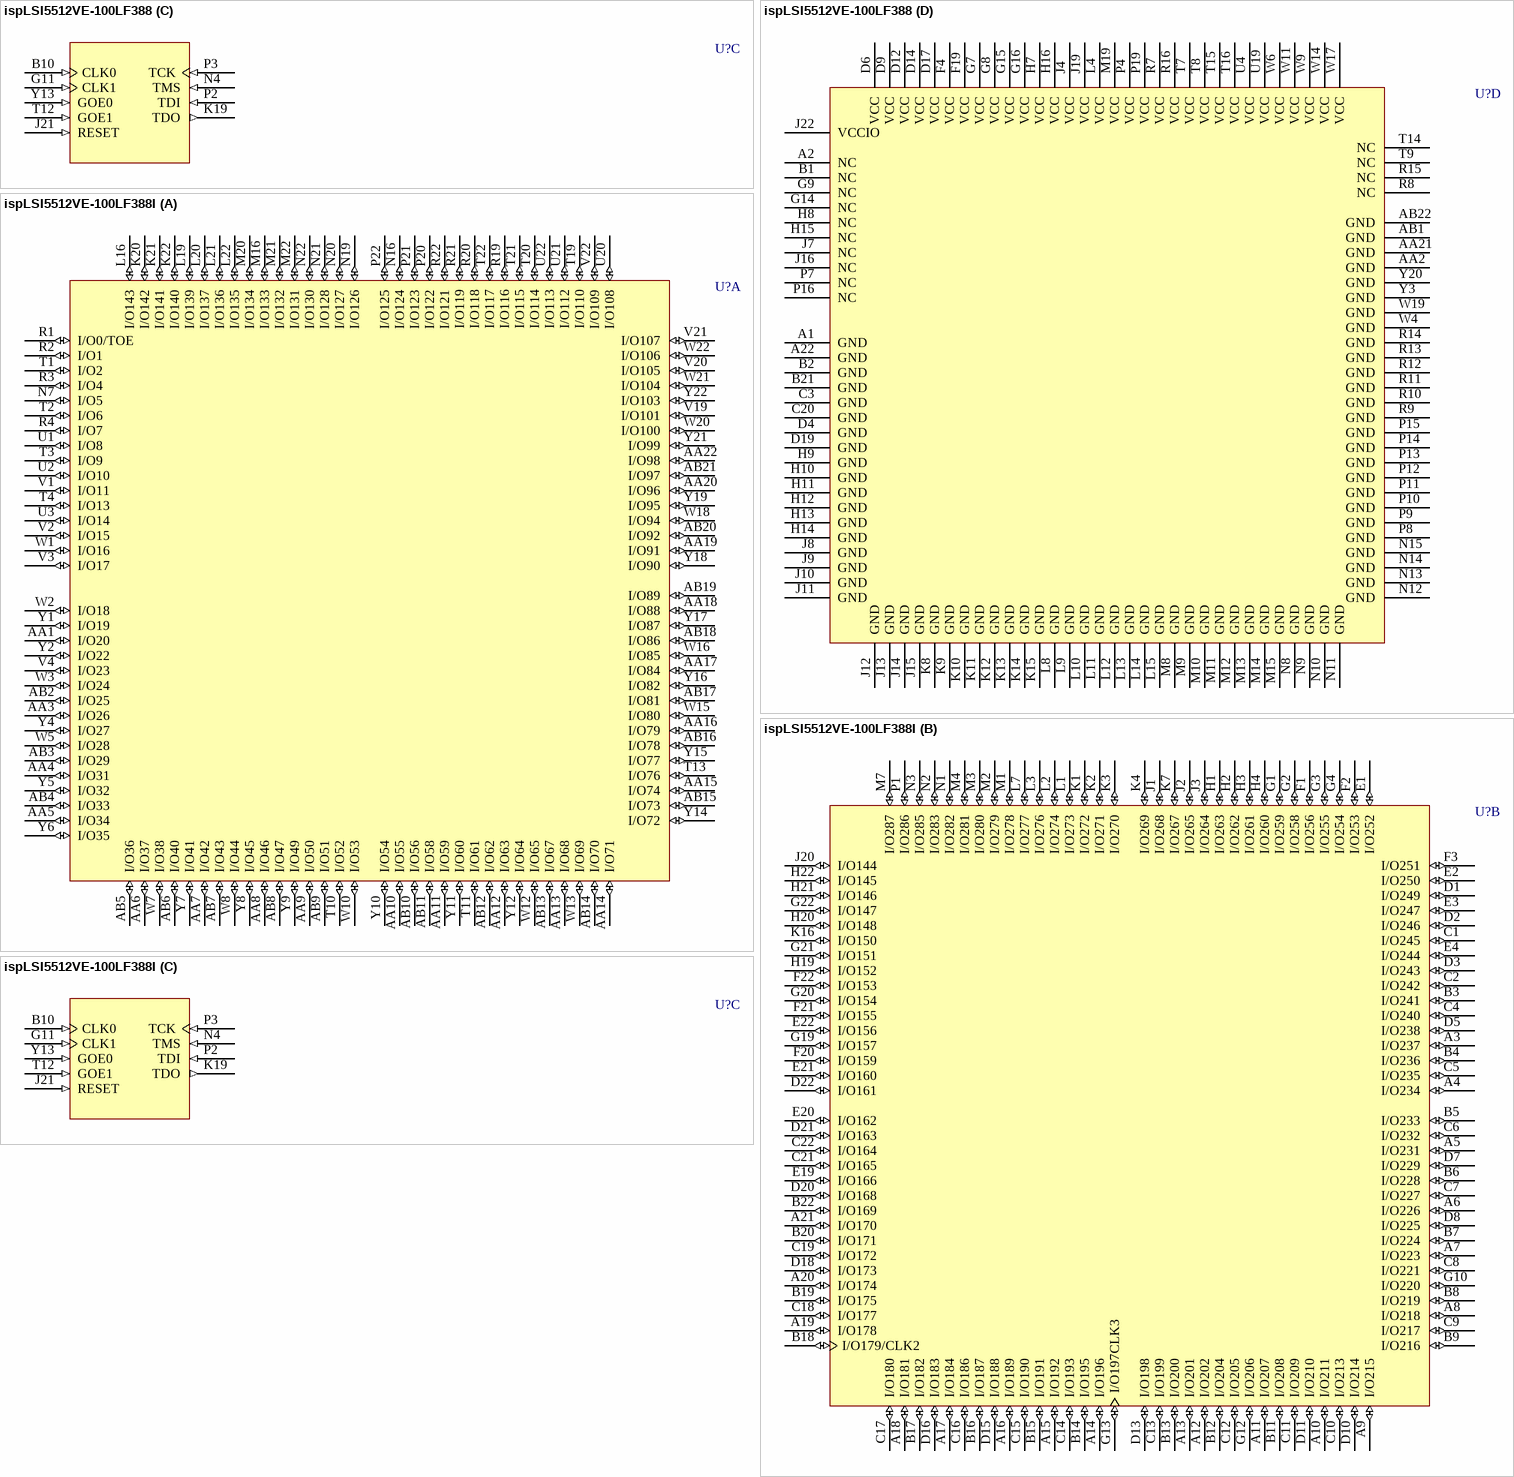
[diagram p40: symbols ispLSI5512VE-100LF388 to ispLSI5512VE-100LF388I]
